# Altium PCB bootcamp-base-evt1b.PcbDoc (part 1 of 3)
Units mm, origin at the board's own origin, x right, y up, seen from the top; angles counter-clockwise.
Board outline 49.31 x 77.41 mm, 4 copper layers (Top Layer, Internal Plane 1, Internal Plane 2, Bottom Layer), stack 1.597 mm thick; 178 components, 122 nets, 1398 pads, 353 vias.
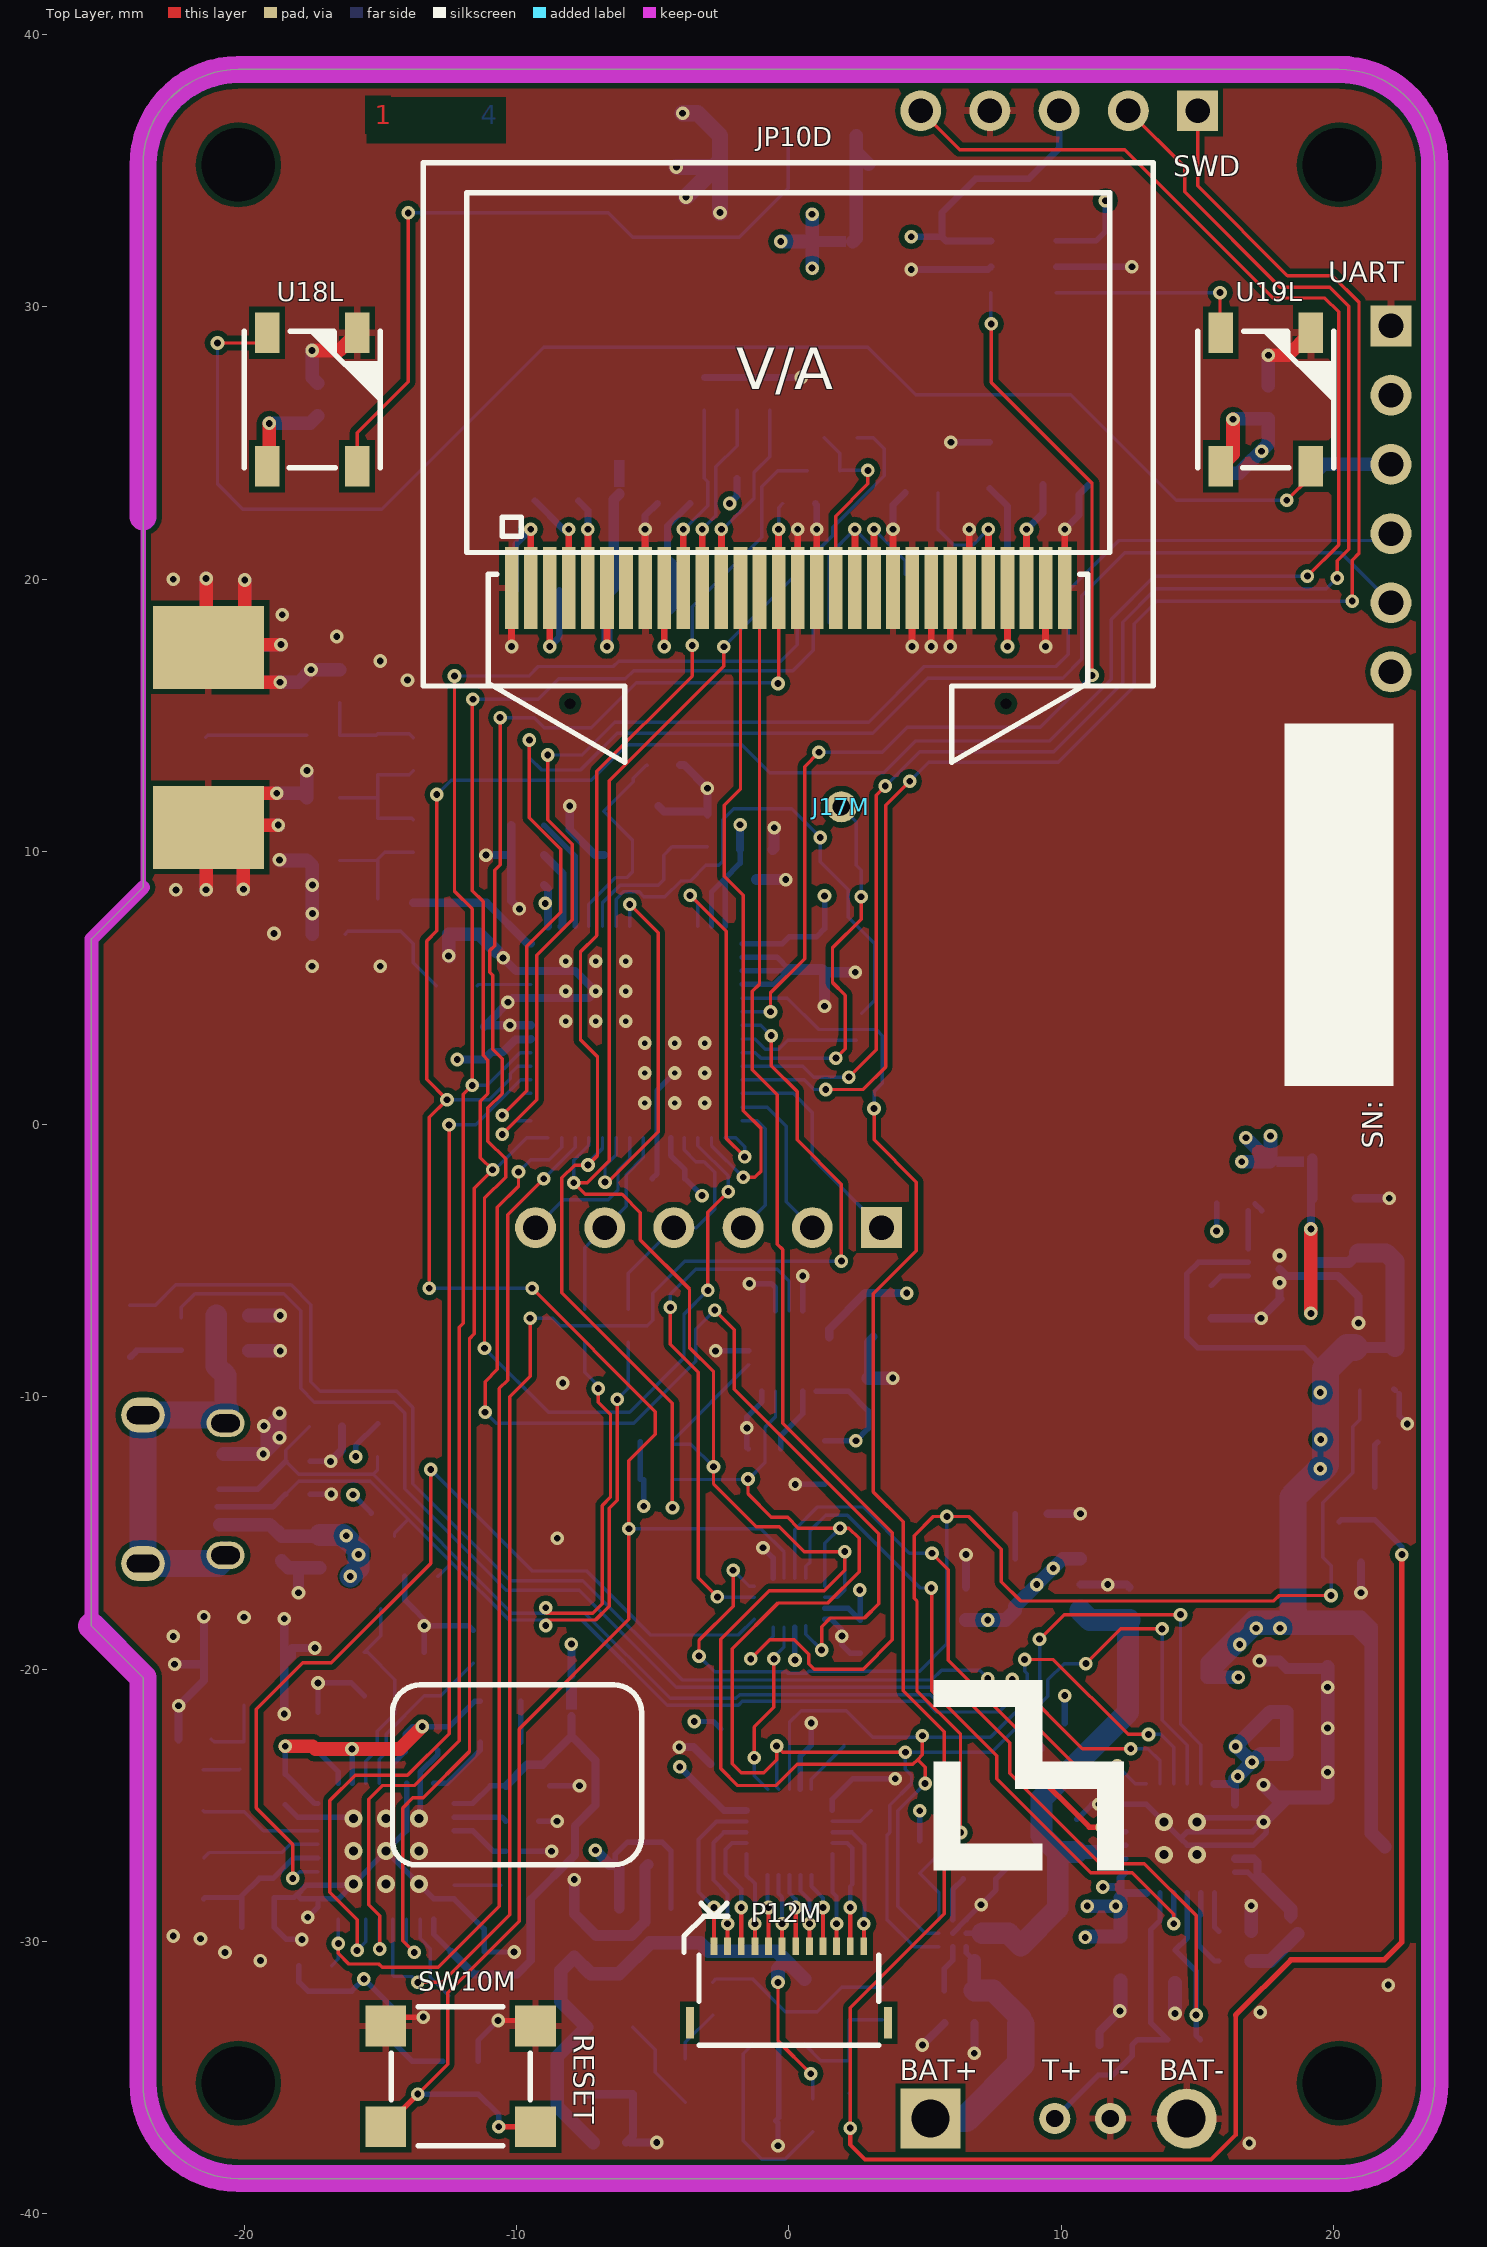
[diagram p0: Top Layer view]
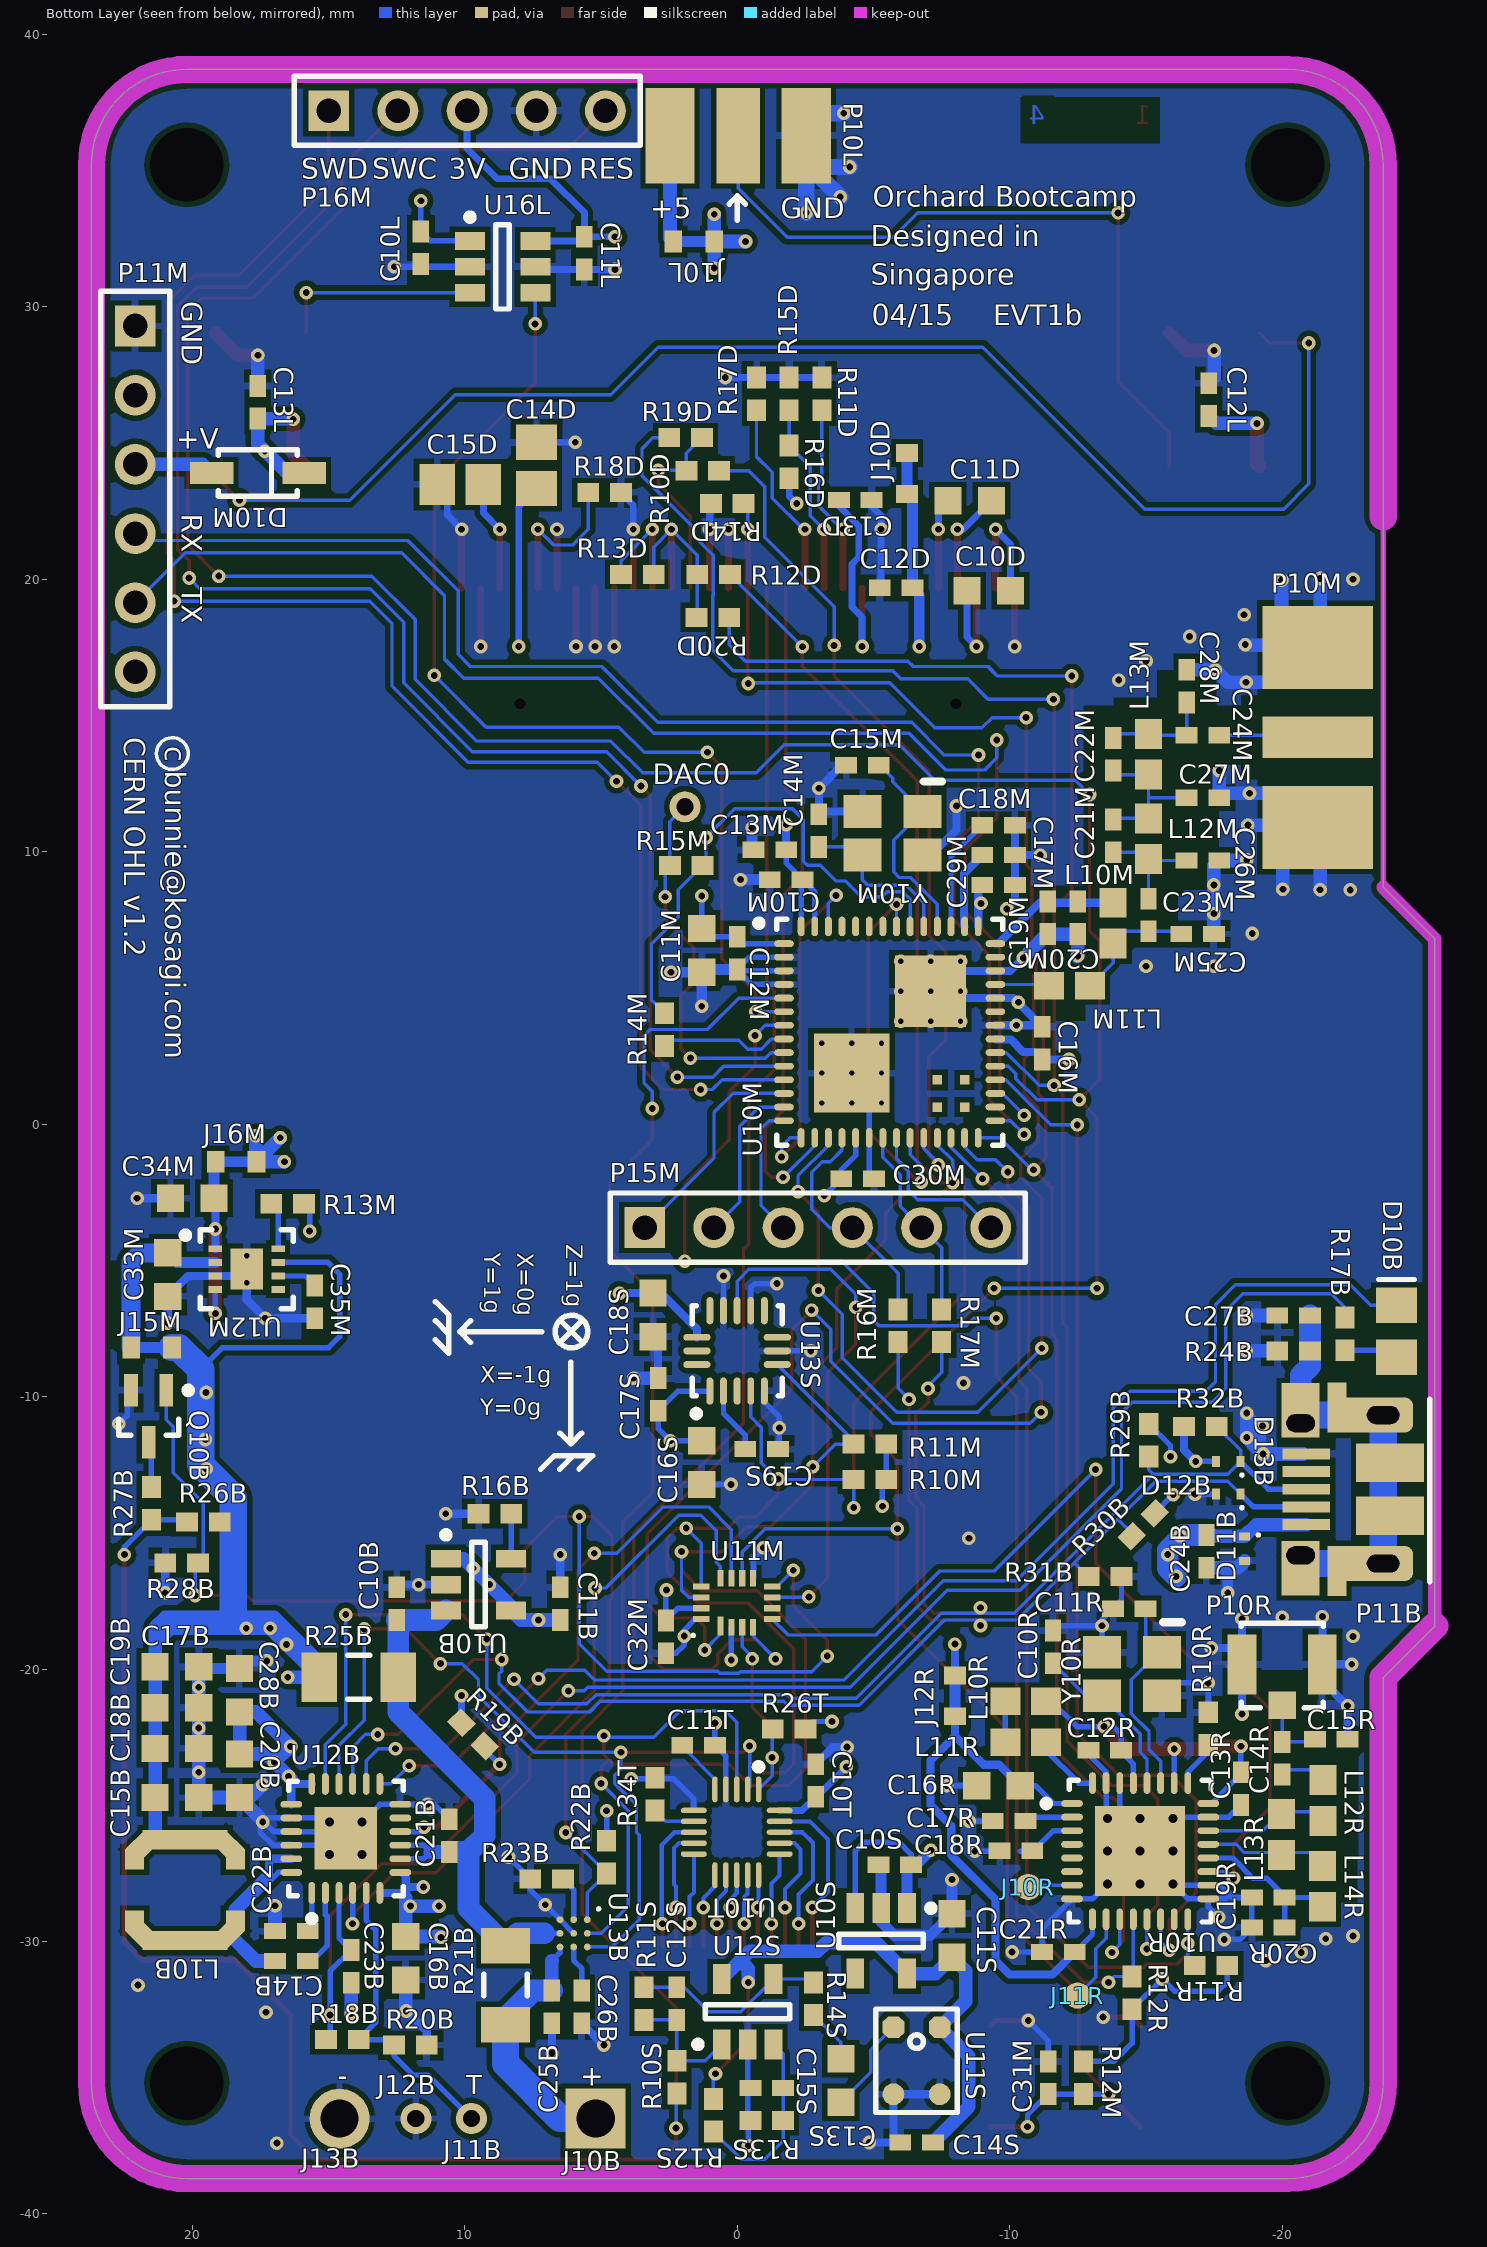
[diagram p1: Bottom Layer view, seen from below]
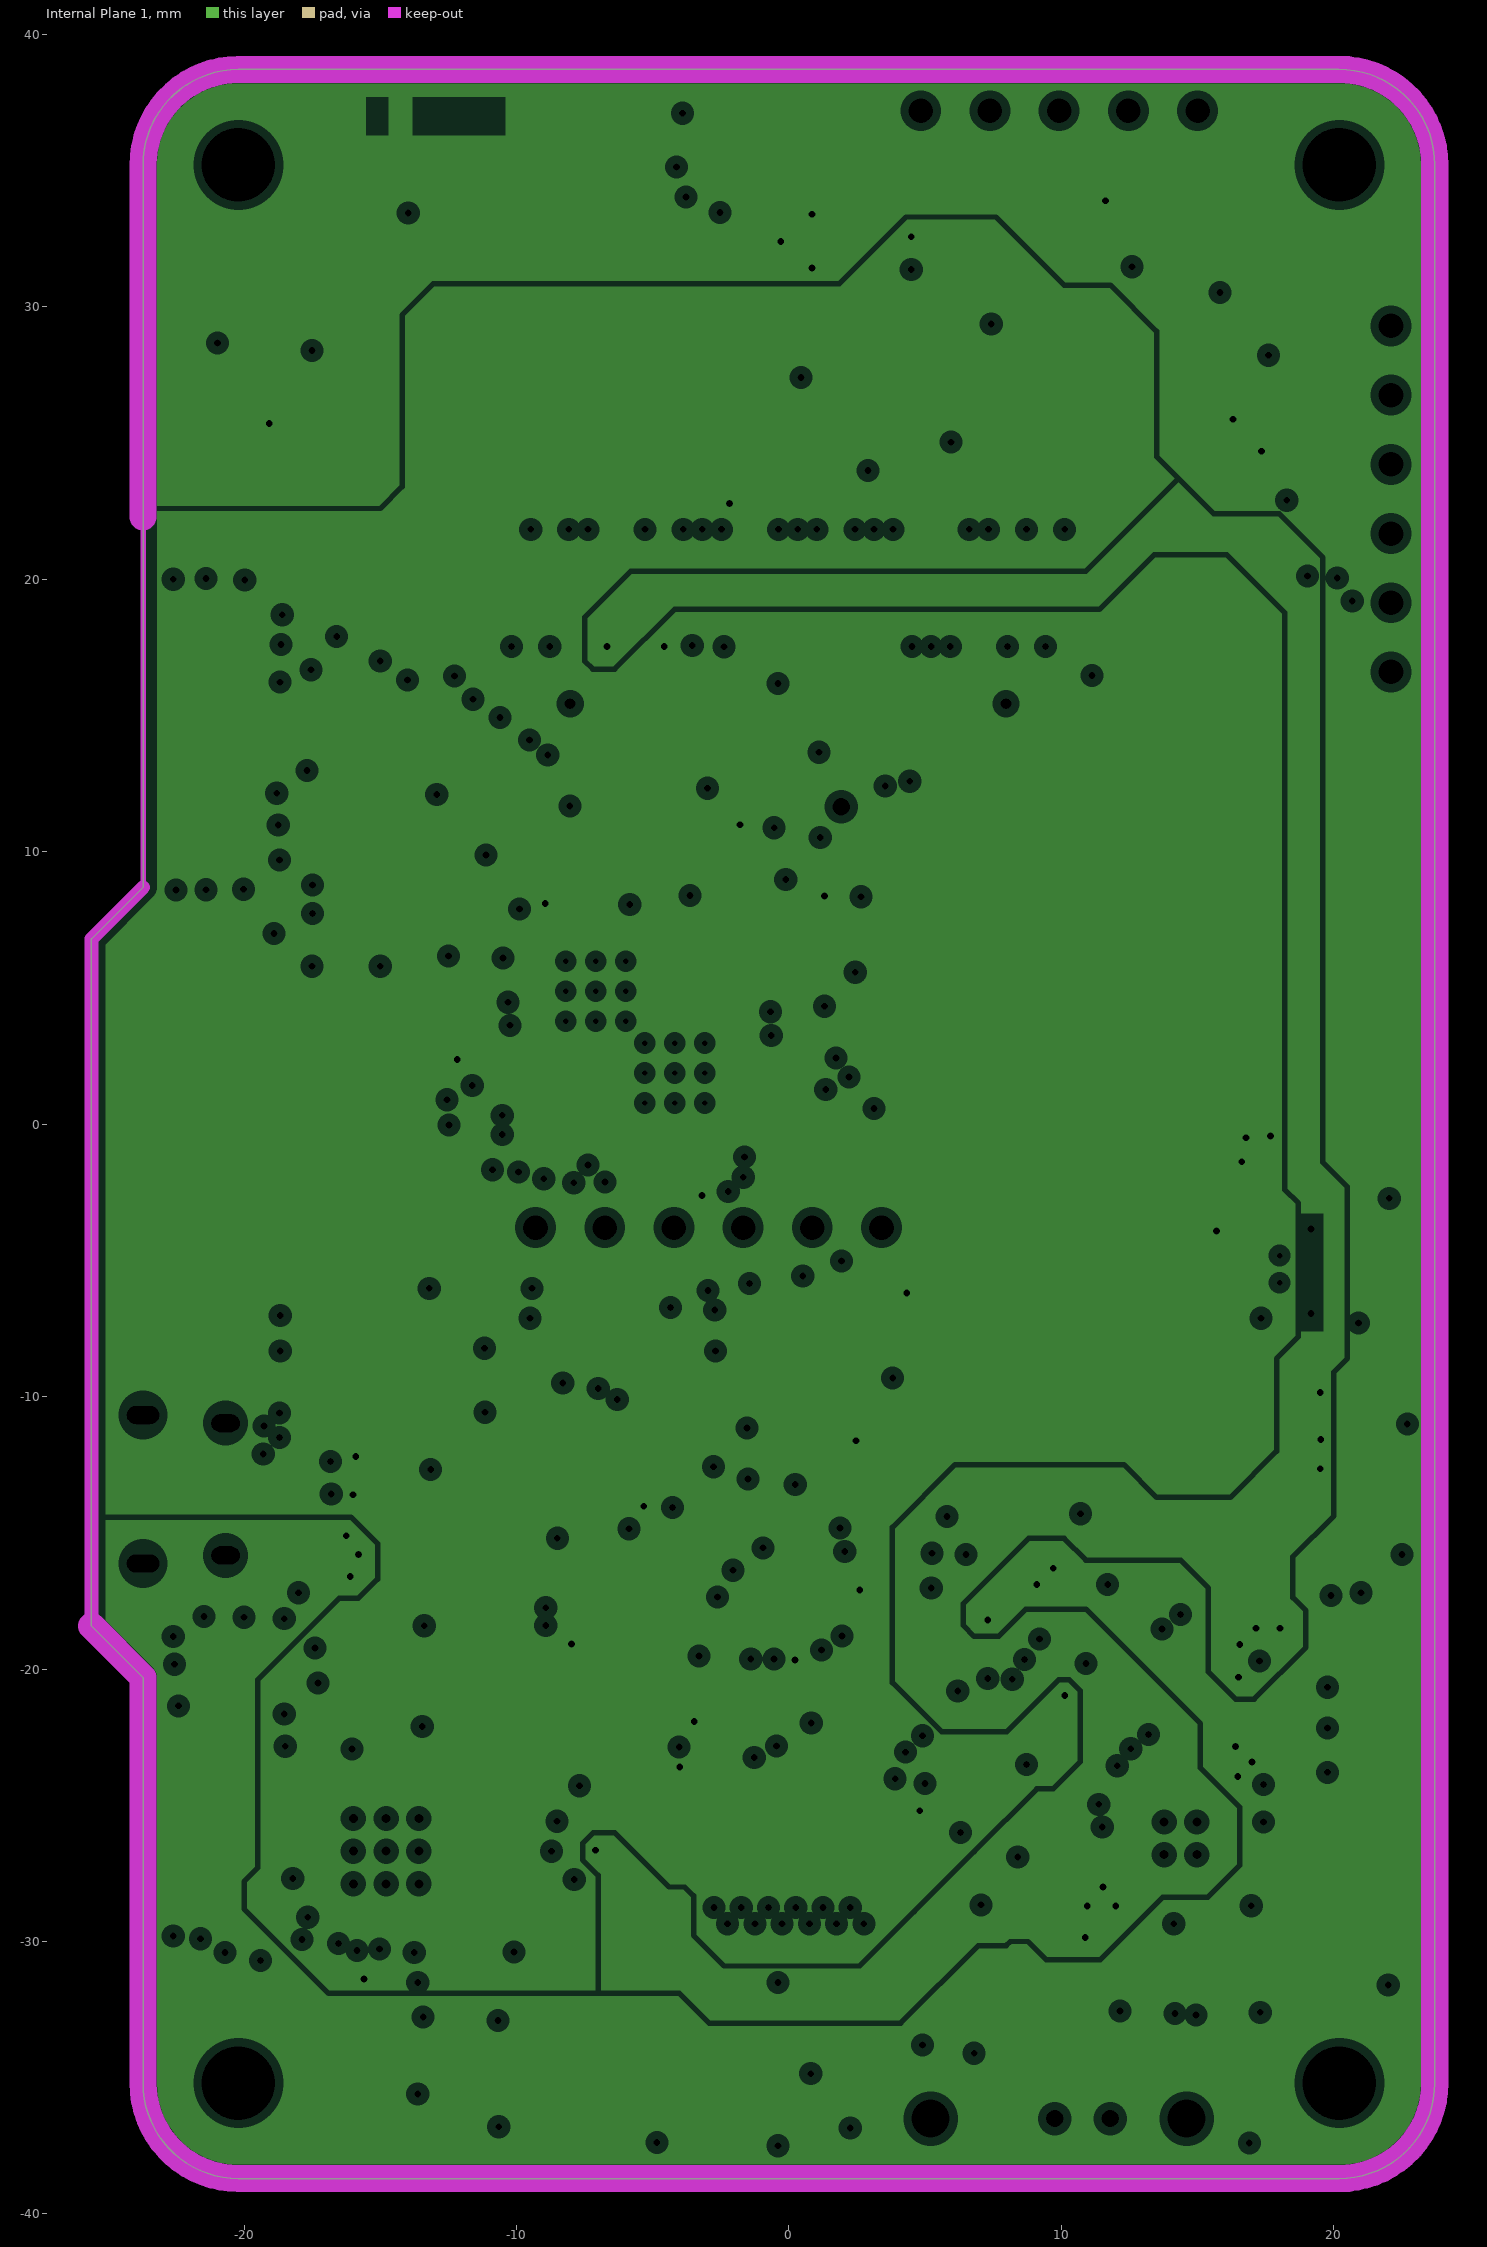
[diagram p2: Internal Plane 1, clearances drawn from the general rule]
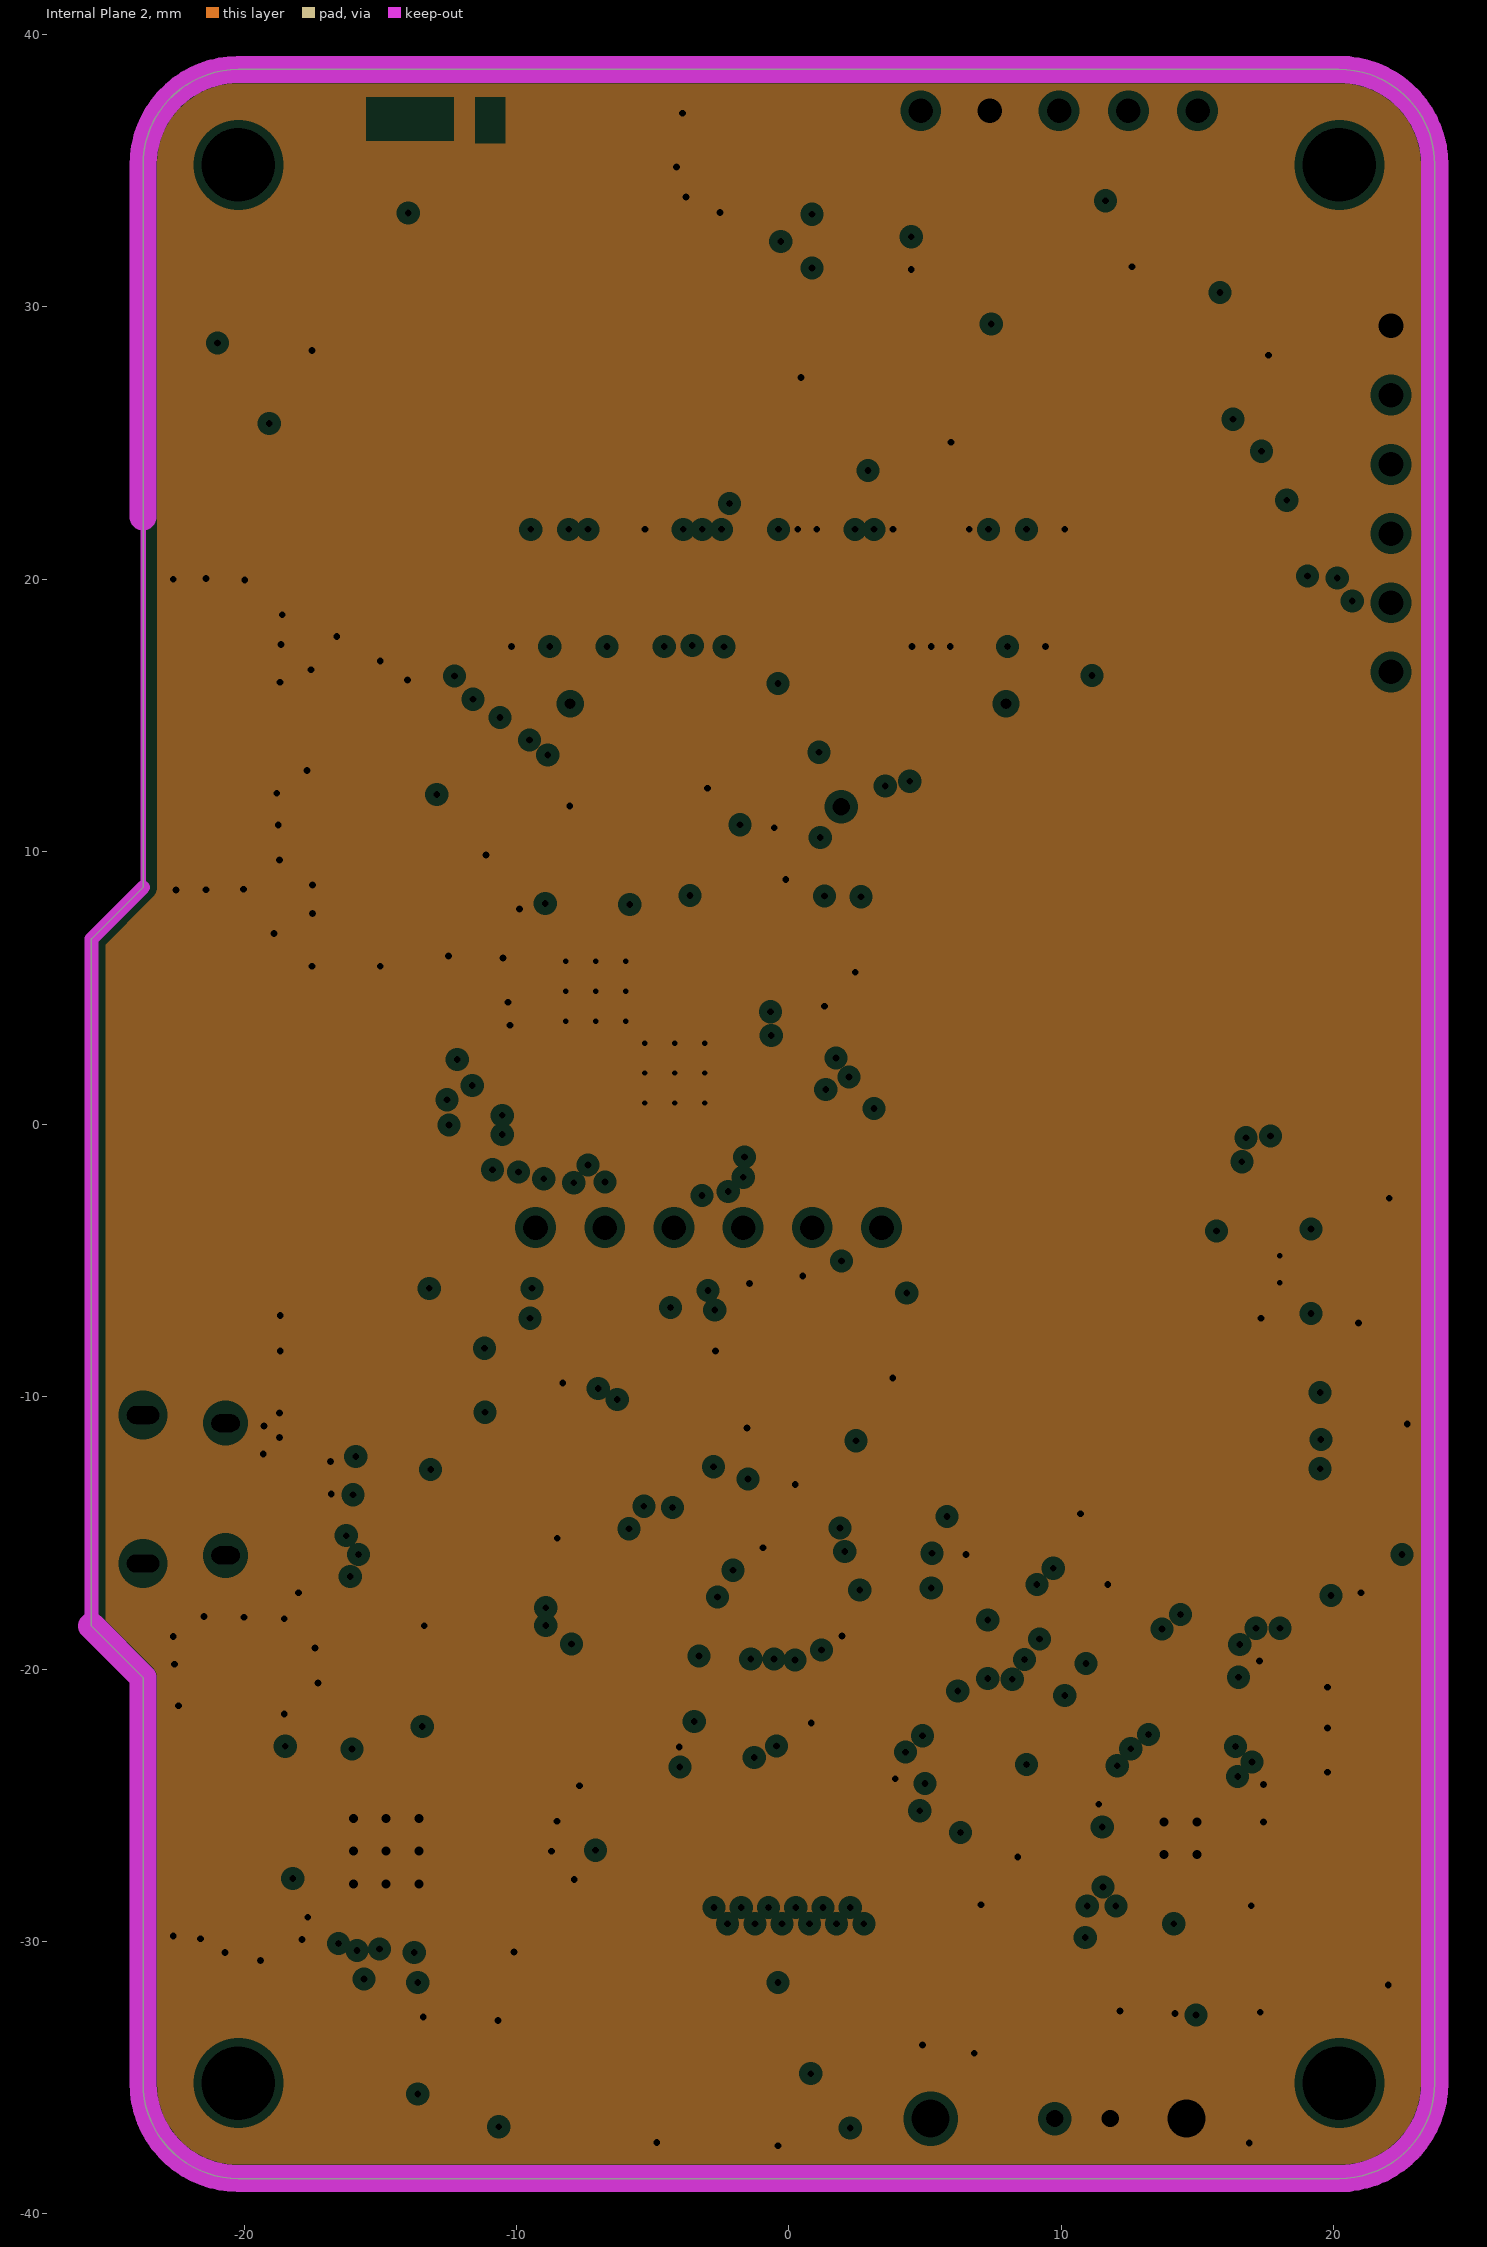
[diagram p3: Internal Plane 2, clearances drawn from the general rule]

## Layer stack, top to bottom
Top Solder: solder mask 0.0102, Solder Resist, Dk 3.5
Top Layer: signal copper 0.0356
Dielectric 1: core 0.1, FR-4, Dk 4.2
Internal Plane 1: plane copper 0.036, net P3.0V
Dielectric 3: prepreg 1.1, Dk 4.2
Internal Plane 2: plane copper 0.036, net GND
Dielectric 2: core 0.254, Dk 4.2
Bottom Layer: signal copper 0.0356
Bottom Solder: solder mask 0.0102, Solder Resist, Dk 3.5

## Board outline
-25.6,-18.417 -23.707,-20.31 -23.707,-35.2 ccw(c-20.207,-35.2) -20.207,-38.7 20.194,-38.7 ccw(c20.207,-35.2) 23.707,-35.2 23.707,-35.186 23.707,35.214 ccw(c20.207,35.214) 20.179,38.714 -20.207,38.714 ccw(c-20.207,35.214) -23.707,35.2 -23.707,8.693 -25.6,6.8

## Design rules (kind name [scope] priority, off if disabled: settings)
AssemblyTestPointUsage [All] p1 off:
AssemblyTestpoint [All] p1 off: testpointundercomponent=TRUE minsize=1.016 maxsize=2.54 preferedsize=1.524 minholesize=0 maxholesize=1.016 preferedholesize=0.813 testpointgrid=0.025 usegrid=TRUE gridtolerance=0 allowsidetop=TRUE allowsidebottom=TRUE
Clearance Poly_bt [InPoly vs InNetClass('RF')] p1: gap=0.8
Clearance Poly_diffpairs [InPoly vs InDifferentialPairClass('All Differential Pairs')] p2: gap=0.63
Clearance Poly_plane [InPoly] p3: gap=0.2
Clearance Pad_NPTH [PadIsPlated = 'False'] p4: gap=0.3
Clearance [All] p5: gap=0.125
ComponentClearance [All] p1 off: gap=0.254 collisioncheckmode=3 verticalgap=0.254 showdistances=FALSE
DiffPairsRouting [All] p1: maxlimit=0.5 minlimit=0.125 mostfreqgap=0.125 toplayer_minwidth=0.1 toplayer_maxwidth=0.1 toplayer_prefwidth=0.1 bottomlayer_minwidth=0.1 bottomlayer_maxwidth=0.1 bottomlayer_prefwidth=0.1 maxuncoupledlength=12.7
HoleSize [All] p1: absolutevalues=TRUE maxlimit=3 minlimit=0.025 maxpercent=80.000 minpercent=20.000
MinimumSolderMaskSliver [All] p1 off: minsoldermaskwidth=0.254
PlaneClearance [All] p1: clearance=0.3
PlaneConnect PlaneConnect_pads [IsPad] p1: planeconnectstyle=Relief reliefexpansion=0.508 reliefentries=4 reliefconductorwidth=0.254 reliefairgap=0.254
PlaneConnect [All] p2: planeconnectstyle=Direct reliefexpansion=0.508 reliefentries=4 reliefconductorwidth=0.254 reliefairgap=0.254
PolygonConnect PolygonConnect_via [IsVia] p1: connectstyle=Direct reliefconductorwidth=0.254 reliefentries=4 polygonreliefangle="90 Angle" airgapwidth=0.254
PolygonConnect [All] p2: connectstyle=Relief reliefconductorwidth=0.25 reliefentries=4 polygonreliefangle="90 Angle" airgapwidth=0.2
RoomDefinition 07captouch [InComponentClass('07captouch')] p1 off: confinementstyle=ConfineIn formatcopy=TRUE lockcomponents=FALSE outline 58.372,-48.063 55.972,-48.063 55.972,-40.863 58.372,-40.863
RoomDefinition 06led [InComponentClass('06led')] p2 off: confinementstyle=ConfineIn formatcopy=TRUE lockcomponents=FALSE outline 64.145,28.5 71.372,28.5 71.372,22.9 64.145,22.9
RoomDefinition 05ble [InComponentClass('05ble')] p3 off: confinementstyle=ConfineIn formatcopy=TRUE lockcomponents=FALSE outline 64.245,33.2 65.672,33.2 65.672,29.4 64.245,29.4
RoomDefinition 03sensors [InComponentClass('03sensors')] p4 off: confinementstyle=ConfineIn formatcopy=TRUE lockcomponents=FALSE outline 64.145,-0.563 63.072,-0.563 63.072,6.637 64.145,6.637
RoomDefinition 02battery [InComponentClass('02battery')] p5 off: confinementstyle=ConfineIn formatcopy=TRUE lockcomponents=FALSE outline 64.145,-19.563 66.572,-19.563 66.572,-1.663 64.145,-1.663
RoomDefinition 01mcu-radio [InComponentClass('01mcu-radio')] p6 off: confinementstyle=ConfineIn formatcopy=TRUE lockcomponents=FALSE outline 64.245,-46.763 71.072,-46.763 71.072,-20.763 64.245,-20.763
RoomDefinition 04oled [InComponentClass('04oled')] p7 off: confinementstyle=ConfineIn formatcopy=TRUE lockcomponents=FALSE outline 62.172,-44.116 60.572,-44.116 60.572,-31.216 62.172,-31.216
RoutingVias [All] p1: holewidth=0.25 width=0.5 viastyle="Through Hole" minholewidth=0.25 minwidth=0.45 maxholewidth=0.38 maxwidth=0.76
SilkToBoardRegionClearance [All] p1 off:
SilkToSilkClearance [All] p1 off: silktosilkclearance=0.254
SilkToSolderMaskClearance [IsPad] p1 off: minsilkscreentomaskgap=0.254 clearancetoexposedcopper=TRUE
SolderMaskExpansion [All] p1: expansion=0.07
Width [All] p1: maxlimit=3 minlimit=0.125 preferedwidth=0.125 minimp=50.000000 maximp=50.000000 favimp=50.000000
18 further rules are at their usual default settings.

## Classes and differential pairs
component class 07captouch: C10T C11T P12M R26T R34T U10T
component class 01mcu-radio: C10M C11M C12M C13M C14M C15M C16M C17M C18M C19M C20M C21M C22M C23M C24M C25M C26M C27M C28M C29M C30M C31M C32M C33M C34M C35M D10M J15M J16M J17M L10M L11M L12M L13M NT10M P10M P11M P15M P16M R10M R11M R12M R13M R14M R15M R16M R17M SW10M U10M U11M U12M Y10M
component class 02battery: C10B C11B C14B C15B C16B C17B C18B C19B C20B C21B C22B C23B C24B C25B C26B C27B C28B D10B D11B D12B D13B J10B J11B J12B J13B L10B NT10B P11B Q10B R16B R17B R18B R19B R20B R21B R22B R23B R24B R25B R26B R27B R28B R29B R30B R31B R32B U10B U12B U13B
component class 03sensors: C10S C11S C12S C13S C14S C15S C16S C17S C18S C19S R10S R11S R12S R13S R14S U10S U11S U12S U13S
component class 04oled: C10D C11D C12D C13D C14D C15D J10D JP10D R10D R11D R12D R13D R14D R15D R16D R17D R18D R19D R20D
component class 05ble: C10R C11R C12R C13R C14R C15R C16R C17R C18R C19R C20R C21R J10R J11R J12R L10R L11R L12R L13R L14R P10R R10R R11R R12R U10R Y10R
component class 06led: C10L C11L C12L C13L J10L P10L U16L U18L U19L
net class RF: BLE_ANT BLE_ANT1 BLE_ANT2 NetC14R_1 NetC21M_1 NetC21M_2 NetC22M_2 NetC24M_2 RFIO

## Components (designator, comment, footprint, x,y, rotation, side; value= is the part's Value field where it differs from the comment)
C10B "1.0uF, 10V, X5R" CAPC1005N 12.5,-17.6 r90 bottom
C10D "1.0uF, 25V, X5R" CAPC1608N -9.228,19.584 r180 bottom
C10L "0.1uF, 25V, X5R" CAPC1005N 11.616,32.172 r270 bottom
C10M "0.1uF, 6.3V, X5R" CAPC1005N -1.792,8.979 r0 bottom
C10R "7.5pF, 50V, NP0, +/-0.5pF" CAPC1005N -11.586,-19.184 r90 bottom
C10S "0.1uF, 6.3V, X5R" CAPC1005N -5.779,-27.177 r0 bottom
C10T "0.1uF, 6.3V, X5R" CAPC1005N -2.878,-24.091 r90 bottom
C11B "1.0uF, 10V, X5R" CAPC1005N 6.5,-17.6 r90 bottom
C11D "1.0uF, 25V, X5R" CAPC1608N -8.528,22.884 r180 bottom
C11L "0.1uF, 6.3V, X5R" CAPC1005N 5.616,31.972 r270 bottom
C11M "10uF, 10V, X5R" CAPC1608N 1.308,6.379 r270 bottom
C11R "7.5pF, 50V, NP0, +/-0.5pF" CAPC1005N -14.386,-17.784 r0 bottom
C11S "4.7uF, 10V, X5R" CAPC1608N -7.879,-29.777 r90 bottom
C11T "0.1uF, 6.3V, X5R" CAPC1005N 1.422,-22.791 r180 bottom
C12D "1.0uF, 10V, X5R" CAPC1005N -5.828,19.684 r0 bottom
C12L "1.0uF, 10V, X5R" CAPC1005N -17.3,26.6 r90 bottom
C12M "0.01uF, 10V, X7R" CAPC1005N 0.008,6.279 r270 bottom
C12R "1.0uF, 10V, X5R" CAPC1005N -13.486,-22.984 r0 bottom
C12S "330pF, 10V, NP0, 5%" CAPC1005N 2.221,-32.277 r90 bottom
C13D "1.0uF, 10V, X5R" CAPC1005N -4.328,22.909 r180 bottom
C13L "1.0uF, 10V, X5R" CAPC1005N 17.6,26.5 r90 bottom
C13M "0.1uF, 6.3V, X5R" CAPC1005N -1.192,10.079 r0 bottom
C13R "1nF, 50V, X7R" CAPC1005N -18.486,-24.384 r270 bottom
C13S "10uF, 10V, X5R" CAPC1608N -3.8,-35.1 r90 bottom
C14B "0.033uF, 16V, X7R" CAPC1005N 16.372,-30.716 r0 bottom
C14D "4.7uF, 25V, X7R" CAPC2012N 7.372,24.184 r90 bottom
C14M "7.5pF, 50V, NP0, +/-0.5pF" CAPC1005N -2.992,10.779 r90 bottom
C14R "1.8pF, 50V, NP0, +/-0.10pF" CAPC1005N -20,-23.275 r90 bottom
C14S "0.1uF, 6.3V, X5R" CAPC1005N -6.579,-37.377 r0 bottom
C15B "10uF, 10V, X5R" CAPC1608N 20.572,-24.716 r180 bottom
C15D "4.7uF, 25V, X7R" CAPC2012N 10.172,23.484 r0 bottom
C15M "7.5pF, 50V, NP0, +/-0.5pF" CAPC1005N -4.592,13.179 r0 bottom
C15R "1.2pF, 50V, NP0, +/-0.10pF" CAPC1005N -21.8,-22.575 r0 bottom
C15S "1.0uF, 10V, X5R" CAPC1005N -1.079,-35.377 r0 bottom
C16B "10uF, 10V, X5R" CAPC1608N 12.172,-30.616 r270 bottom
C16M "0.1uF, 6.3V, X5R" CAPC1005N -11.192,2.979 r90 bottom
C16R "4.7uF, 10V, X5R" CAPC1608N -9.586,-24.284 r0 bottom
C16S "10uF, 10V, X5R" CAPC1608N 1.308,-12.421 r270 bottom
C17B "10uF, 10V, X5R" CAPC1608N 20.572,-19.916 r180 bottom
C17M "0.1uF, 6.3V, X5R" CAPC1005N -9.592,9.879 r180 bottom
C17R "0.1uF, 6.3V, X5R" CAPC1005N -9.975,-25.575 r0 bottom
C17S "0.1uF, 6.3V, X5R" CAPC1005N 2.908,-9.921 r90 bottom
C18B "10uF, 10V, X5R" CAPC1608N 20.572,-22.916 r180 bottom
C18M "0.1uF, 6.3V, X5R" CAPC1005N -9.592,10.979 r180 bottom
C18R "0.033uF, 16V, X7R" CAPC1005N -10.225,-26.675 r180 bottom
C18S "10uF, 10V, X5R" CAPC1608N 3.1,-7 r270 bottom
C19B "10uF, 10V, X5R" CAPC1608N 20.572,-21.416 r180 bottom
C19M "0.1uF, 6.3V, X5R" CAPC1005N -11.392,7.579 r270 bottom
C19R "2200pF, 50V, X7R" CAPC1005N -19.486,-28.384 r180 bottom
C19S "0.1uF, 6.3V, X5R" CAPC1005N -0.892,-11.921 r180 bottom
C20B "10uF, 10V, X5R" CAPC1608N 18.272,-23.916 r270 bottom
C20M "220pF, 10V, NP0, 5%" CAPC1005N -12.492,7.579 r270 bottom
C20R "DNP" CAPC1005N -19.486,-29.484 r180 bottom
C21B "1.0uF, 10V, X5R" CAPC1005N 10.572,-26.116 r90 bottom
C21M "0402 DNP" CAPC1005N -13.792,10.579 r90 bottom
C21R "0.1uF, 6.3V, X5R" CAPC1005N -11.786,-30.384 r0 bottom
C22B "1.0uF, 10V, X5R" CAPC1005N 16.372,-29.616 r0 bottom
C22M "0402 DNP" CAPC1005N -13.792,13.579 r90 bottom
C23B "1.0uF, 10V, X5R" CAPC1005N 14.172,-30.916 r270 bottom
C23M "6.8pF, 50V, NP0, +/-0.5pF" CAPC1005N -15.092,7.679 r90 bottom
C24B "0.1uF, 25V, X5R" CAPC1005N -17.223,-15.679 r270 bottom
C24M "100pF, 50V, NP0, 5%" CAPC1005N -17.092,14.279 r180 bottom
C25B "1.0uF, 10V, X5R" CAPC1005N 6.808,-32.4 r270 bottom
C25M "2.0pF, 50V, NP0, +/-0.25pF" CAPC1005N -16.892,6.979 r180 bottom
C26B "1.0uF, 10V, X5R" CAPC1005N 5.708,-32.4 r270 bottom
C26M "0402 DNP" CAPC1005N -17.092,9.679 r0 bottom
C27B "0.1uF, 25V, X5R" CAPC1005N -20.421,-7.023 r0 bottom
C27M "7.5pF, 50V, NP0, +/-0.5pF" CAPC1005N -17.092,11.979 r180 bottom
C28B "10uF, 10V, X5R" CAPC1608N 18.275,-20.775 r90 bottom
C28M "5.6pF, 50V, NP0, +/-0.25pF" CAPC1005N -16.492,16.079 r90 bottom
C29M "0.1uF, 6.3V, X5R" CAPC1005N -9.592,8.779 r180 bottom
C30M "0.1uF, 6.3V, X5R" CAPC1005N -4.417,-1.996 r180 bottom
C31M "0.01uF, 10V, X7R" CAPC1005N -11.408,-35 r90 bottom
C32M "0.1uF, 6.3V, X5R" CAPC1005N 2.621,-18.817 r270 bottom
C33M "4.7uF, 10V, X5R" CAPC1608N 20.908,-5.521 r270 bottom
C34M "4.7uF, 10V, X5R" CAPC1608N 20.008,-2.721 r0 bottom
C35M "0.033uF, 16V, X7R" CAPC1005N 15.508,-6.521 r90 bottom
D10B "White LED" CD2012-0805 -24.2,-7.6 r90 bottom
D10M "B140HW-7" SOD123 17.6,23.9 r180 bottom
D11B "ESD9B5.0ST5G" SOD-923 -18.623,-15.579 r270 bottom
D12B "ESD9B5.0ST5G" SOD-923 -18.023,-13.579 r0 bottom
D13B "ESD9B5.0ST5G" SOD-923 -18.023,-12.379 r0 bottom
J10B "wire hole" TP_HOLE#1 5.2,-36.5 r90 bottom
J10D "power tap (DNP)" RESTAP-0603 -6.228,23.884 r90 bottom
J10L "power tap (DNP)" RESTAP-0603 1.6,32.4 r0 bottom
J10R "test point (DNP)" TP_SMT_38mil -10.675,-28 r90 bottom
J11B "wire hole" TP_HOLE#2 9.76,-36.5 r180 bottom
J11R "test point (DNP)" TP_SMT_38mil -12.486,-31.984 r90 bottom
J12B "wire hole" TP_HOLE#2 11.8,-36.5 r0 bottom
J12R "power tap (DNP)" RESTAP-0603 -7.986,-20.984 r270 bottom
J13B "wire hole" TP_HOLE#3 14.6,-36.5 r270 bottom
J15M "power tap (DNP)" RESTAP-0603 21.5,-8.2 r180 bottom
J16M "power tap (DNP)" RESTAP-0603 18.4,-1.379 r180 bottom
J17M "wire hole" TP_HOLE#2 1.925,11.65 r180 top
JP10D "ER-OLED0.96-3W" ER-OLED0.96-FOLD -0.028,20.184 r0 top locked
L10B "2.2uH LPS4018-222" COILCRAFT_LPS4018 20.272,-28.116 r90 bottom
L10M "33nH 5% Q>8" INDC1608AN -13.792,7.379 r270 bottom
L10R "15nH, Q>35, 5%" INDC1608AN -10.586,-21.184 r180 bottom
L11M "4.7nH+/-0.3nH Q>8" INDC1608AN -12.192,5.079 r180 bottom
L11R "10uH, 300mA" INDC1608AN -10.586,-22.684 r0 bottom
L12M "6.8nH 5% Q>8" INDC1608AN -15.092,10.479 r90 bottom
L12R "3.9nH+/-0.3nH Q>8" INDC1608AN -21.5,-24.825 r90 bottom
L13M "6.8nH 5% Q>8" INDC1608AN -15.092,13.579 r90 bottom
L13R "8.2nH+/-0.3nH Q>8" INDC1608AN -19.975,-26.075 r270 bottom
L14R "5.6nH+/-0.3nH Q>8" INDC1608AN -21.475,-27.975 r270 bottom
P10L "WS2812B-PAD" LED_STRIP_PADS_SHORT -0.028,36.284 r270 bottom
P10M "SMA Edge Launch" SMA_EDGELAUNCH -21.307,14.2 r180 bottom
P10R "U.FL KAWEEI P1163-0140R" HRS_U.FL -20,-19.825 r180 bottom
P11B "FCI 10103594-0001LF" USB_MICRO_B_SMT -23.707,-13.4 r90 bottom
P11M "Male 2.54mm 6x1 header (DNP)" HDR1X6 22.1,29.3 r270 bottom
P12M "KAWEEI THD0510-12RL-GF" KAWEEI_THD0510_12RL_GF 0,-30.5 r0 top
P15M "2.54mm header, 6 pin" HDR1X6 3.398,-3.796 r180 bottom
P16M "Header 5" HDR1X5 15,37.2 r180 bottom
Q10B "2N7002W (DNP)" SOT323-3AN 21.608,-10.721 r270 bottom
R10D "0 ohm (DNP)" RESC1005N 1.272,23.984 r180 bottom
R10M "4.7k, 1%" RESC1005N -4.863,-13.041 r180 bottom
R10R "22k, 1%" RESC1005N -17.286,-22.184 r270 bottom
R10S "2.2k, 1%" RESC1005N 2.221,-34.977 r90 bottom
R11D "10k, 1%" RESC1005N -3.103,26.809 r270 bottom
R11M "4.7k, 1%" RESC1005N -4.863,-11.741 r180 bottom
R11R "4.7k, 1%" RESC1005N -17.386,-30.884 r180 bottom
R11S "22k, 1%" RESC1005N 3.421,-32.277 r270 bottom
R12D "0 ohm (DNP)" RESC1005N 0.872,20.184 r180 bottom
R12M "1k, 1%" RESC1005N -12.708,-35 r270 bottom
R12R "4.7k, 1%" RESC1005N -14.486,-31.884 r270 bottom
R12S "47k, 1%" RESC1005N 0.877,-36.379 r90 bottom
R13D "0 ohm (DNP)" RESC1005N 3.672,20.184 r180 bottom
R13M "100k, 1%" RESC1005N 16.508,-2.921 r0 bottom
R13S "47k, 1%" RESC1005N -1.079,-36.577 r180 bottom
R14D "10k, 1% (DNP)" RESC1005N 0.372,22.784 r0 bottom
R14M "0 ohm" RESC1005N 2.675,3.475 r270 bottom
R14S "2.2k, 1%" RESC1005N -2.8,-32.1 r270 bottom
R15D "10k, 1%" RESC1005N -1.903,26.809 r270 bottom
R15M "0 ohm (DNP)" RESC1005N 1.875,9.5 r0 bottom
R16B "2k, 1%" RESC1005N 8.9,-14.3 r0 bottom
R16D "10k, 1% (DNP)" RESC1005N -1.903,24.309 r90 bottom
R16M "0 ohm" RESC1005N -5.9,-7.4 r90 bottom
R17B "470, 1%" RESC1005N -22.3,-7.7 r270 bottom
R17D "10k, 1%" RESC1005N -0.703,26.809 r270 bottom
R17M "0 ohm" RESC1005N -7.5,-7.4 r90 bottom
R18B "9.76k, 1%" RESC1005N 14.5,-33.6 r0 bottom
R18D "390k, 1%" RESC1005N 4.872,23.184 r180 bottom
R19B "47k, 1%" RESC1005N 9.7,-22.4 r45 bottom
R19D "0 ohm" RESC1005N 1.9,25.2 r0 bottom
R20B "34.8k, 1%" RESC1005N 12,-33.8 r0 bottom
R20D "0 ohm" RESC1005N 0.9,18.6 r180 bottom
R21B "0 ohm 1206 (DNP)" RESC3216N 8.508,-31.6 r270 bottom
R22B "10k, 1%" RESC1005N 4.8,-26.9 r90 bottom
R23B "10k, 1%" RESC1005N 7,-27.7 r180 bottom
R24B "100, 1%" RESC1005N -20.421,-8.323 r0 bottom
R25B "0 ohm 1206 (DNP)" RESC3216N 13.9,-20.3 r0 bottom
R26B "10k, 1% (DNP)" RESC1005N 19.6,-14.6 r180 bottom
R26T "4.7k, 1%" RESC1005N -1.9,-22.2 r180 bottom
R27B "10k, 1% (DNP)" RESC1005N 21.508,-13.921 r270 bottom
R28B "10k, 1% (DNP)" RESC1005N 20.4,-16.1 r180 bottom
R29B "10k, 1% (DNP)" RESC1005N -15.1,-11.6 r90 bottom
R30B "1.5k, 1% (DNP)" RESC1005N -14.9,-14.7 r135 bottom
R31B "100k, 1% (DNP)" RESC1005N -13.5,-16.6 r180 bottom
R32B "DNP" RESC1005N -17,-11.1 r0 bottom
R34T "75k, 1%" RESC1005N 3.022,-24.591 r270 bottom
SW10M "5x5mm 1.6mm tall PB" SWITCH_TS-1187A -9.3,-33.1 r270 top
U10B "MCP73812T-420I/OT (DNP)" SOT-23-OT5_N 9.5,-16.9 r180 bottom
U10M "MKW01Z128CHN" KINETIS_W_QFN50P800X800X98_HS-57N -5.592,3.379 r180 bottom
U10R "NRF8001" QFN50P500X500-32VAN -14.786,-26.684 r180 bottom
U10S "LP2980IM5-3.0" SOT23-5AN -5.279,-29.977 r270 bottom
U10T "MPR121" QFN40P300X300X60-20N 0.022,-25.991 r270 bottom
U11M "FXL6408UMX" FAIRCHILD_UMLP16 0.021,-17.567 r90 bottom
U11S "SPU0409HD5H-PB" KNOWLES_SPU0409HD5H-PB -6.579,-34.377 r180 bottom
U12B "BQ24260RGET" QFN50P400X400-24VBN 14.372,-26.216 r90 bottom
U12M "LP3982ILD-3.0" LDA08C 18.008,-5.321 r180 bottom
U12S "FAN4174IS5X" SOT23-5AN -0.379,-32.577 r90 bottom
U13B "BQ27421YZFT-G1A" TI_YZF_S_XBGA_N9 6.008,-29.7 r270 bottom
U13S "MMA8452QR1" FSC_QFN_3x3x1_16_2077-02 0.008,-8.321 r90 bottom
U16L "SN74LVC1T45DBV" SOT26A-6N 8.616,31.472 r180 bottom
U18L "WS2812B" WS2812B -17.5,26.6 r90 top
U19L "WS2812B" WS2812B 17.5,26.6 r90 top
Y10M "32.000MHz" NDK_NX3225SA -6.792,11.479 r0 bottom
Y10R "16.000MHz" NDK_NX3225SA -15.586,-19.384 r0 bottom

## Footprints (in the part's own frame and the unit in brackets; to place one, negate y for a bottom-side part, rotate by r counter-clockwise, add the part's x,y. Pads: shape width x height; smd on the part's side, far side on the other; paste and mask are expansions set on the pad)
CAPC1005N [mm] "Chip Capacitor, Body 1.0x0.5mm, IPC Medium Density"
  rect 0.8x0.6 smd: 1(-0.6,0) 2(0.6,0)
  body extent -0.55,-0.3 0.55,0.3, height 0.6
CAPC1608N [mm] "Chip Capacitor, Body 1.6x0.8mm, IPC Medium Density"
  rect 1x1 smd: 1(-0.8,0) 2(0.8,0)
  body extent -0.87,-0.48 0.87,0.48, height 0.85
CAPC2012N [mm] "Chip Capacitor, Body 2.0x1.3mm, IPC Medium Density"
  rect 1.3x1.5 smd: 1(-0.85,0) 2(0.85,0)
  body extent -1.1,-0.72 1.1,0.72, height 1.1
CD2012-0805 [mm] "Chip Diode; Body 2.0 x 1.3 mm (LxW typ)"
  rect 1.3x1.5 smd: 1(-0.95,0) 2(0.95,0)
  silkscreen extent 1.9,-0.65 1.9,0.65
COILCRAFT_LPS4018 [mm] "Coilcraft SMT power inductor, shielded, high current"
  rect 0.7x3.124 smd mask+0.07: 1(-1.85,0) 2(1.85,0)
  rect 0.7x1 smd rot 135 mask+0.07: 1(-1.6,1.6) 2(1.6,-1.6)
  rect 0.7x1 smd rot 45 mask+0.07: 1(-1.6,-1.6) 2(1.6,1.6)
  rect 0.75x0.7 smd mask+0.07: 1(-1.125,-1.85) 1(-1.125,1.85) 2(1.125,-1.85) 2(1.125,1.85)
  body extent -2.05,-2.05 2.05,2.05, height 1.8
ER-OLED0.96-FOLD [mm] "ER-OLED 0.96in Direct to PCB mount, folded"
  round 0.2 hole 0.4 unplated mask+0.3: 0(-8,-4.75) 0(8,-4.75)
  rect 0.5x3 smd mask+0.07: 1(-10.15,-0.5) 2(-9.45,-0.5) 3(-8.75,-0.5) 4(-8.05,-0.5) 5(-7.35,-0.5) 6(-6.65,-0.5) 7(-5.95,-0.5) 8(-5.25,-0.5) 9(-4.55,-0.5) 10(-3.85,-0.5) 11(-3.15,-0.5) 12(-2.45,-0.5) 13(-1.75,-0.5) 14(-1.05,-0.5) 15(-0.35,-0.5) 16(0.35,-0.5) 17(1.05,-0.5) 18(1.75,-0.5) 19(2.45,-0.5) 20(3.15,-0.5) 21(3.85,-0.5) 22(4.55,-0.5) 23(5.25,-0.5) 24(5.95,-0.5) 25(6.65,-0.5) 26(7.35,-0.5) 27(8.05,-0.5) 28(8.75,-0.5) 29(9.45,-0.5) 30(10.15,-0.5)
  silkscreen extent -13.4,-6.9 13.4,15.1, body extent -13.4,-4.1 13.4,15.1, height 1.61
FAIRCHILD_UMLP16 [mm] "Fairchild 16-pin UMLP"
  rect 0.7x0.225 smd mask+0.07: 1(-0.85,0.6)
  rect 0.6x0.225 smd mask+0.07: 2(-0.9,0.2) 3(-0.9,-0.2) 4(-0.9,-0.6) 9(0.9,-0.6) 10(0.9,-0.2) 11(0.9,0.2) 12(0.9,0.6)
  rect 0.225x0.6 smd mask+0.07: 5(-0.6,-1.3) 6(-0.2,-1.3) 7(0.2,-1.3) 8(0.6,-1.3) 13(0.6,1.3) 14(0.2,1.3) 15(-0.2,1.3) 16(-0.6,1.3)
  silkscreen extent -1.25,1.55 -1.15,1.65, body extent -0.9,-1.3 0.9,1.3, height 0.55
FSC_QFN_3x3x1_16_2077-02 [mm] "16-pin non-standard Freescale QFN package"
  oval 1x0.25 smd mask+0.07: 1(-1.475,1) 2(-1.475,0.5) 3(-1.475,0) 4(-1.475,-0.5) 5(-1.475,-1) 9(1.475,-1) 10(1.475,-0.5) 11(1.475,0) 12(1.475,0.5) 13(1.475,1)
  oval 0.25x1 smd mask+0.07: 6(-0.5,-1.475) 7(0,-1.475) 8(0.5,-1.475) 14(0.5,1.475) 15(0,1.475) 16(-0.5,1.475)
  silkscreen extent -2.42,-1.65 1.65,1.65, body extent -1.5,-1.5 1.5,1.5, height 1
HDR1X5 [mm] "Connector; Header; 5 Position"
  rect 1.5x1.5 hole 0.9: 1(0,0)
  round 1.5 hole 0.9: 2(2.54,0) 3(5.08,0) 4(7.62,0) 5(10.16,0)
  silkscreen extent -1.27,-1.27 11.43,1.27
HDR1X6 [mm] "Connector; Header; 6 Position"
  rect 1.5x1.5 hole 0.9: 1(0,0)
  round 1.5 hole 0.9: 2(2.54,0) 3(5.08,0) 4(7.62,0) 5(10.16,0) 6(12.7,0)
  silkscreen extent -1.27,-1.27 13.97,1.27
HRS_U.FL [mm] "6 GHz U.FL connector (ISM band antennas)"
  rect 1.05x2.2 smd: GND(-1.475,0) GND(1.475,0)
  rect 1x1 smd: SIG(0,-1.5)
  silkscreen extent -1.5,-1.6 1.5,1.5, body extent -1.5,-1.6 1.5,1.5, height 1.24
INDC1608AN [mm] "Chip Inductor, Body 1.6x0.8mm, IPC Medium Density"
  rect 1.1x1 smd: 1(-0.75,0) 2(0.75,0)
  body extent -0.9,-0.5 0.9,0.5, height 1
KAWEEI_THD0510_12RL_GF [mm] "FPC, 12 pins, 0.5mm pitch, bottom contacts"
  rect 0.3x1.15 smd mask+0.07: 0(-3.635,-2.485) 0(3.635,-2.485)
  rect 0.25x0.65 smd mask+0.07: 1(-2.75,0.325) 2(-2.25,0.325) 3(-1.75,0.325) 4(-1.25,0.325) 5(-0.75,0.325) 6(-0.25,0.325) 7(0.25,0.325) 8(0.75,0.325) 9(1.25,0.325) 10(1.75,0.325) 11(2.25,0.325) 12(2.75,0.325)
  silkscreen extent -3.85,-3.3 3.3,1.9, body extent -3.3,-3.3 3.3,0.38, height 1
KINETIS_W_QFN50P800X800X98_HS-57N [mm] "QFN, 56-Leads, Body 8.00x8.00mm, Pitch 0.50mm, Thermal Pad 6.60x6.40mm, IPC Medium Density"
  oval 0.72x0.25 smd mask+0.07: 1(-3.88,3.25) 2(-3.88,2.75) 3(-3.88,2.25) 4(-3.88,1.75) 5(-3.88,1.25) 6(-3.88,0.75) 7(-3.88,0.25) 8(-3.88,-0.25) 9(-3.88,-0.75) 10(-3.88,-1.25) 11(-3.88,-1.75) 12(-3.88,-2.25) 13(-3.88,-2.75) 14(-3.88,-3.25) 29(3.88,-3.25) 30(3.88,-2.75) 31(3.88,-2.25) 32(3.88,-1.75) 33(3.88,-1.25) 34(3.88,-0.75) 35(3.88,-0.25) 36(3.88,0.25) 37(3.88,0.75) 38(3.88,1.25) 39(3.88,1.75) 40(3.88,2.25) 41(3.88,2.75) 42(3.88,3.25)
  oval 0.25x0.72 smd mask+0.07: 15(-3.25,-3.88) 16(-2.75,-3.88) 17(-2.25,-3.88) 18(-1.75,-3.88) 19(-1.25,-3.88) 20(-0.75,-3.88) 21(-0.25,-3.88) 22(0.25,-3.88) 23(0.75,-3.88) 24(1.25,-3.88) 25(1.75,-3.88) 26(2.25,-3.88) 27(2.75,-3.88) 28(3.25,-3.88) 43(3.25,3.88) 44(2.75,3.88) 45(2.25,3.88) 46(1.75,3.88) 47(1.25,3.88) 48(0.75,3.88) 49(0.25,3.88) 50(-0.25,3.88) 51(-0.75,3.88) 52(-1.25,3.88) 53(-1.75,3.88) 54(-2.25,3.88) 55(-2.75,3.88) 56(-3.25,3.88)
  rect 0.35x0.35 smd mask+0.07: 57(1.75,-1.75) 58(2.75,-1.75) 59(1.75,-2.75) 60(2.75,-2.75)
  rect 2.62x2.62 smd mask+0.07: 61(1.5,1.5)
  rect 2.77x2.9 smd mask+0.07: 62(-1.4,-1.5)
  silkscreen extent -4.93,-4.15 4.15,4.15, body extent -4,-4 4,4, height 0.98
KNOWLES_SPU0409HD5H-PB [mm] "Silicon MEMS microphone"
  oct 0.8x0.8 smd: 1(0.85,1.23) 4(-0.85,1.23)
  round 0.8 smd: 2(0.85,-1.23) 3(-0.85,-1.23)
  silkscreen extent -1.5,-1.9 1.5,1.9, body extent -1.5,-1.9 1.5,1.9, height 1.1
LDA08C [mm] "PSON, 8-Leads, Body 2.5x3mm, Pitch 0.5mm, NSC Recommended"
  rect 0.5x0.25 smd paste-0.125 mask+0.051: 1(-1.15,0.75) 2(-1.15,0.25) 3(-1.15,-0.25) 4(-1.15,-0.75) 5(1.15,-0.75) 6(1.15,-0.25) 7(1.15,0.25) 8(1.15,0.75)
  rect 1.2x1.5 smd paste-0.6 mask+0.051: 9(0,0)
  silkscreen extent -2.38,-1.45 1.7,1.45, body extent -1.55,-1.3 1.55,1.3, height 0.8
LED_STRIP_PADS_SHORT [mm] "Solder pads for WS2812B-style strips"
  rect 3.5x1.8 smd: 1(0,2.5) 3(0,-2.5)
  rect 3.5x1.6 smd: 2(0,0)
NDK_NX3225SA [mm] "3.2x2.5mm crystal"
  rect 1.4x1.2 smd: 1(0,0) 2(2.2,1.6) 3(2.2,0) 4(0,1.6)
  silkscreen extent -0.72,-1.1 -0.05,-1.1, body extent -0.6,-0.5 2.8,2.1, height 0.7
QFN40P300X300X60-20N [mm] "QFN, 20-Leads, Body 3.0x3.0mm (max), Pitch 0.40mm, IPC Medium Density"
  oval 0.95x0.2 smd mask+0.07: 1(-1.575,0.8) 2(-1.575,0.4) 3(-1.575,0) 4(-1.575,-0.4) 5(-1.575,-0.8) 11(1.575,-0.8) 12(1.575,-0.4) 13(1.575,0) 14(1.575,0.4) 15(1.575,0.8)
  oval 0.2x0.95 smd mask+0.07: 6(-0.8,-1.575) 7(-0.4,-1.575) 8(0,-1.575) 9(0.4,-1.575) 10(0.8,-1.575) 16(0.8,1.575) 17(0.4,1.575) 18(0,1.575) 19(-0.4,1.575) 20(-0.8,1.575)
  silkscreen extent -2.52,0.68 -2.28,0.92, body extent -1.5,-1.5 1.5,1.5, height 0.6
QFN50P400X400-24VBN [mm] "QFN, 24-Leads, Body 4x4mm, Pitch 0.5mm, IPC Medium Density"
  oval 0.8x0.25 smd: 1(-2,1.25) 2(-2,0.75) 3(-2,0.25) 4(-2,-0.25) 5(-2,-0.75) 6(-2,-1.25) 13(2,-1.25) 14(2,-0.75) 15(2,-0.25) 16(2,0.25) 17(2,0.75) 18(2,1.25)
  oval 0.25x0.8 smd: 7(-1.25,-2) 8(-0.75,-2) 9(-0.25,-2) 10(0.25,-2) 11(0.75,-2) 12(1.25,-2) 19(1.25,2) 20(0.75,2) 21(0.25,2) 22(-0.25,2) 23(-0.75,2) 24(-1.25,2)
  rect 2.3x2.3 smd: 25(0,0)
  silkscreen extent -3.07,-2.1 2.1,2.1, body extent -2.07,-2.07 2.07,2.07, height 1
QFN50P500X500-32VAN [mm] "QFN, 32-Leads, Body 5x5mm, Pitch 0.5mm, IPC Medium Density"
  oval 0.8x0.25 smd mask+0.075: 1(-2.5,1.75) 2(-2.5,1.25) 3(-2.5,0.75) 4(-2.5,0.25) 5(-2.5,-0.25) 6(-2.5,-0.75) 7(-2.5,-1.25) 8(-2.5,-1.75) 17(2.5,-1.75) 18(2.5,-1.25) 19(2.5,-0.75) 20(2.5,-0.25) 21(2.5,0.25) 22(2.5,0.75) 23(2.5,1.25) 24(2.5,1.75)
  oval 0.25x0.8 smd mask+0.075: 9(-1.75,-2.5) 10(-1.25,-2.5) 11(-0.75,-2.5) 12(-0.25,-2.5) 13(0.25,-2.5) 14(0.75,-2.5) 15(1.25,-2.5) 16(1.75,-2.5) 25(1.75,2.5) 26(1.25,2.5) 27(0.75,2.5) 28(0.25,2.5) 29(-0.25,2.5) 30(-0.75,2.5) 31(-1.25,2.5) 32(-1.75,2.5)
  rect 3.3x3.3 smd mask+0.075: 33(0,0)
  silkscreen extent -3.58,-2.6 2.6,2.6, body extent -2.58,-2.58 2.58,2.58, height 1
RESC1005N [mm] "Chip Resistor, Body 1.1x0.5mm, IPC Medium Density"
  rect 0.8x0.7 smd: 1(-0.6,0) 2(0.6,0)
  body extent -0.55,-0.3 0.55,0.3, height 0.4
RESC3216N [mm] "Chip Resistor, Body 3.2x1.6mm, IPC Medium Density"
  rect 1.3x1.8 smd: 1(-1.45,0) 2(1.45,0)
  silkscreen extent -0.4,-0.8 0.4,0.8, body extent -1.68,-0.87 1.67,0.87, height 0.71
RESTAP-0603 [mm] "0603 Power tap, cut-trace style"
  rect 0.65x0.8 smd: 1(-0.75,0) 1(0.75,0)
  Top Layer region: -0.504,0.2 0.496,0.2 0.496,-0.2 -0.504,-0.2
  body extent -0.8,-0.4 0.8,0.4, height 0.8
SMA_EDGELAUNCH [mil] "SMA Edge Launch, Generic"
  rect 160x60 smd: 1(0,0)
  rect 160x120 smd far side: 2(0,-130) 2(0,130)
  rect 160x120 smd: 2(0,-130) 2(0,130)
  body extent -75,-188 587,187, height 171
SOD123 [mm] "SOD-123; 2 Leads; Body 2.7 x 1.6 mm, (LxW)"
  rect 1.6x0.8 smd: 1(-1.7,0) 2(1.7,0)
  silkscreen extent -1.45,-0.85 1.45,0.85
SOD-923 [mm] "Molded Diode, 2-Leads, Body 0.80x0.60mm, IPC Medium Density"
  rect 0.3x0.4 smd: 1(-0.45,0) 2(0.45,0)
  silkscreen extent -0.55,0.45 -0.45,0.55, body extent -0.43,-0.33 0.42,0.33, height 0.4
SOT23-5AN [mm] "SOT23, 5-Leads, Body 2.9x1.6mm, Pitch 0.95mm, Lead Span 2.8mm, IPC Medium Density"
  rect 1.1x0.65 smd mask+0.075: 1(-1.2,0.95) 2(-1.2,0) 3(-1.2,-0.95) 4(1.2,-0.95) 5(1.2,0.95)
  silkscreen extent -1.32,-1.55 0.25,1.95, body extent -0.9,-1.55 0.9,1.55, height 1.45
SOT26A-6N [mm] "SOT23, 6-Leads, Body 2.9x1.7mm, Pitch 0.95mm, Lead Span 2.8mm, IPC Medium Density"
  rect 1.1x0.65 smd: 1(-1.2,0.95) 2(-1.2,0) 3(-1.2,-0.95) 4(1.2,-0.95) 5(1.2,0) 6(1.2,0.95)
  silkscreen extent -1.33,-1.55 0.25,1.95, body extent -0.9,-1.55 0.9,1.55, height 1.45
SOT323-3AN [mm] "SOT323, 3-Leads, Body 2.0x1.3mm, Pitch 0.65mm, Lead Span 2.1mm, IPC Medium Density"
  rect 1.2x0.5 smd: 1(-0.95,0.65) 2(-0.95,-0.65) 3(0.95,0)
  silkscreen extent -1.07,-1.1 0.7,1.57, body extent -0.7,-1.1 0.7,1.1, height 1
SOT-23-OT5_N [mm] "SOT23, 5-Leads, Body 2.9x1.6mm, Pitch 0.95mm, Lead Span 2.7mm, IPC Medium Density"
  rect 1.1x0.65 smd: 1(-1.2,0.95) 2(-1.2,0) 3(-1.2,-0.95) 4(1.2,-0.95) 5(1.2,0.95)
  silkscreen extent -1.33,-1.55 0.25,1.95, body extent -0.9,-1.55 0.9,1.55, height 1.45
SWITCH_TS-1187A [mm] "TS-1187A tact switch, Chi Fung Electronics"
  rect 1.5x1.5 smd mask+0.07: 1(0,0) 2(0,-5.5) 3(3.7,0) 4(3.7,-5.5)
  silkscreen extent -0.7,-5.3 4.4,-0.2, body extent -0.7,-5.3 4.4,-0.2, height 1.6
TI_YZF_S_XBGA_N9 [mm] "BGA, 9-Leads, Body 1.58x1.62mmx0.63mm, Pitch 0.50mm"
  round 0.25 smd mask+0.07: A1(-0.5,0.5) A2(0,0.5) A3(0.5,0.5) B1(-0.5,0) B2(0,0) B3(0.5,0) C1(-0.5,-0.5) C2(0,-0.5) C3(0.5,-0.5)
  silkscreen extent -0.94,0.86 -0.85,0.96, body extent -0.79,-0.81 0.79,0.81, height 0.63
TP_HOLE#1 [mm] "Bare wire test point hole"
  rect 2.2x2.2 hole 1.4: 1(0,0)
TP_HOLE#2 [mm] "Bare wire test point hole"
  round 1.143 hole 0.635: 1(0,0)
TP_HOLE#3 [mm] "Bare wire test point hole"
  round 2.2 hole 1.4: 1(0,0)
TP_SMT_38mil [mil] "38 mil round test point, SMT"
  round 38 smd: 1(0,0)
USB_MICRO_B_SMT [mm] "Micro B SMT footprint (based on USB-IF recommended pattern)"
  rect 1.825x0.7 smd mask+0.07: 0(-3,1.7) 0(3,1.7)
  rect 2x1.4 smd mask+0.07: 0(-2.9,3.03) 0(2.9,3.03)
  rrect50% 1.3x3.15 smd mask+0.07: 0(-2.725,0.475) 0(2.725,0.475)
  oval 1.3x1.6 hole 0.66 slot 1.2 at 90 deg mask+0.07: 0(-2.725,0) 0(2.725,0)
  oval 1x1.4 hole 0.66 slot 1.05 at 90 deg mask+0.07: 0(-2.425,3.03) 0(2.425,3.03)
  rect 1.425x2.5 smd mask+0.07: 0(-0.975,-0.25) 0(0.975,-0.25)
  rect 0.4x1.75 smd mask+0.07: 1(-1.3,2.825) 2(-0.65,2.825) 3(0,2.825) 4(0.65,2.825) 5(1.3,2.825)
  silkscreen extent -3.4,-1.7 3.3,-1.7, body extent -4.02,-2.75 4.02,3.28, height 2.85
WS2812B [mm] "3-color RGB LED with internal controller"
  rect 1.5x0.9 smd: 1(-2.45,1.65) 2(-2.45,-1.65) 3(2.45,-1.65) 4(2.45,1.65)
  silkscreen extent -2.5,-2.5 2.5,2.5, body extent -2.5,-2.5 2.5,2.5, height 1.5

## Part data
C10B C10D C10L C10M C10R C10S C10T C11B C11D C11L C11M C11R C11S C11T C12D C12L C12M C12R C12S C13D C13L C13M C13R C13S C14B C14D C14M C14R C14S C15B C15D C15M C15R C15S C16B C16M C16R C16S C17B C17M C17R C17S C18B C18M C18R C18S C19B C19M C19R C19S C20B C20M C20R C21B C21M C21R C22B C22M C23B C23M C24B C24M C25B C25M C26B C26M C27B C27M C28B C28M C29M C30M C31M C32M C33M C34M C35M: library part "Cap Semi", "Capacitor (Semiconductor SIM Model)"
D10B: library part LED2, "White LED 0805"
D10M: library part "D Schottky", "Schottky Diode"
D11B D12B D13B: library part Tranzorb, "TVS Diode, 5V"
J10B J10D J10L J10R J11B J11R J12B J12R J13B J15M J16M J17M: library part CON1, "Connector"
JP10D: "0.96in OLED, 128x64, white"
L10B: library part "Inductor Iron", "Magnetic-Core Inductor"
L10M L10R L11M L11R L12M L12R L13M L13R L14R: library part Inductor, "chip inductor, 0603"
P10L: library part "Header 3", "Header, 3-Pin"
P10M: library part BNC, "50 ohm SMA Edge Launch Connector"
P10R: library part BNC, "U.FL connector"
P11B: library part USB_MINI-AB_1, "Micro USB B type connector"
P11M P15M: library part "Header 6", "Header, 6-Pin"
P12M: library part "Header 12", "Header, 12-Pin"
P16M: "Header, 5-Pin"
Q10B: library part MOSFET-N, "N-Channel MOSFET"
R10D R10M R10R R10S R11D R11M R11R R11S R12D R12M R12R R12S R13D R13M R13S R14D R14M R14S R15D R15M R16B R16D R16M R17B R17D R17M R18B R18D R19B R19D R20B R20D R21B R22B R23B R24B R25B R26B R26T R27B R28B R29B R30B R31B R32B R34T: library part Res1, "Resistor"
SW10M: library part "Header 4", "Chi Fung TS-1187A"
U10B: library part MCP73812T-420I/OT, "Simple, Miniature Single-Cell, Fully Integrated Li-Ion/Li-Polymer Charge Management Controller, 4.2V, 5-Pin SOT-23, Industrial Temperature, Tape and Reel"
U10M: "Freescale Kinetis Integrated Radio + MCU, < 1GHz"
U10R: "BLE single-chip solution"
U10S: library part LP2980M5, "50 mA SOT-23 regulator"
U10T: "Freescale 12-electrode captouch switch sensor IC"
U11M: library part FXL6408, "8-bit I2C GPIO expander"
U11S: "Knowles MEMS silicon microphone"
U12B: library part BQ24260/1/2RGE, "3A, 30V host-controlled single cell Li-ion battery charger"
U12M: "Micropower, Ultra Low-Dropout, Low-Noise, 300mA CMOS Regulator"
U12S: "Rail-to-rail single CMOS op-amp, 5V, 3.7MHz GBW"
U13B: "System-side Impedance Track Gas Gauge"
U13S: "3-axis, 12-bit/8-bit digital accelerometer"
U16L: library part SN74LVC1T45, "Single-gate level translator"
U18L U19L: "RGB LED with integrated controller IC"
Y10M Y10R: library part XTAL, "32 MHz, 7pF CL 10ppm 3225 SMD crystal"

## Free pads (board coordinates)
  round 2.5 hole 2.7 unplated paste-5 mask+2: 0(-20.207,-35.2) 0(-20.207,35.214) 0(20.207,-35.2) 0(20.207,35.214)
  rect 0.203x0.051 on Top Overlay: 1(-13.89,-25.687) 1(-12.925,-24.062) 1(-12.874,-21.674) 1(-12.773,-21.522) 1(-12.468,-22.334) 1(-12.315,-26.703) 1(-11.655,-22.639) 1(-11.503,-24.112) 1(-11.503,-21.826) 1(-11.401,-21.674) 1(-11.35,-21.623) 1(-11.299,-21.522) 1(-11.249,-21.471) 1(-11.198,-21.318) 1(-11.147,-22.284) 1(-11.147,-21.268) 1(-11.096,-22.233) 1(-11.045,-22.182) 1(-10.995,-22.131) 1(-10.741,-21.776) 1(-10.741,-21.725) 1(-10.69,-21.674) 1(-10.639,-21.572) 1(-10.588,-25.586) 1(-10.588,-21.522) 1(-10.588,-21.471) 1(-9.42,-21.877) 1(-9.217,-21.42) 1(-8.658,-21.115) 1(-8.505,-22.944) 1(-8.505,-21.268) 1(-8.455,-21.826) 1(-8.404,-21.776) 1(-8.404,-20.963) 1(-8.353,-21.725) 1(-8.302,-21.674) 1(-8.302,-21.064) 1(-8.251,-21.115) 1(-7.845,-24.112) 1(-7.794,-24.062) 1(-7.794,-22.487) 1(-7.743,-23.96) 1(-7.693,-21.522) 1(-7.642,-22.385) 1(-7.591,-21.674) 1(-7.439,-23.3) 1(-7.439,-22.233) 1(-7.388,-22.182) 1(-7.337,-22.131) 1(-7.286,-22.08) 1(-7.235,-22.03) 1(-7.185,-22.334) 1(-7.185,-21.979) 1(-7.134,-21.928) 1(-7.083,-21.877) 1(-7.032,-21.826) 1(-6.88,-22.588) 1(-6.778,-26.043) 1(-6.727,-24.062) 1(-6.321,-26.043)
  rect 0.254x0.051 on Top Overlay: 1(-13.865,-25.636) 1(-13.814,-25.586) 1(-13.763,-25.535) 1(-13.763,-22.436) 1(-13.712,-25.484) 1(-13.712,-22.385) 1(-13.662,-25.433) 1(-13.611,-25.382) 1(-13.611,-22.334) 1(-13.56,-25.332) 1(-13.509,-22.284) 1(-13.458,-25.179) 1(-13.458,-22.233) 1(-13.408,-25.128) 1(-13.357,-22.182) 1(-13.306,-22.131) 1(-13.255,-22.08) 1(-13.204,-22.03) 1(-13.154,-21.979) 1(-13.001,-21.826) 1(-12.95,-21.776) 1(-12.9,-24.112) 1(-12.9,-21.725) 1(-12.849,-21.623) 1(-12.798,-21.979) 1(-12.798,-21.572) 1(-12.747,-21.471) 1(-12.646,-22.08) 1(-12.595,-22.131) 1(-12.544,-22.182) 1(-12.493,-22.284) 1(-12.493,-22.233) 1(-12.29,-26.652) 1(-12.138,-22.995) 1(-11.579,-22.588) 1(-11.477,-22.538) 1(-11.426,-24.163) 1(-11.426,-22.487) 1(-11.376,-24.214) 1(-11.325,-24.265) 1(-11.325,-22.436) 1(-11.274,-22.385) 1(-11.223,-22.334) 1(-11.172,-21.115) 1(-11.122,-21.217) 1(-11.122,-21.166) 1(-10.664,-21.623) 1(-10.563,-25.535) 1(-10.563,-21.42) 1(-9.801,-24.62) 1(-9.75,-24.57) 1(-9.699,-26.703) 1(-9.699,-21.623) 1(-9.496,-21.776) 1(-9.445,-21.826) 1(-9.445,-21.217) 1(-9.394,-22.538) 1(-9.293,-21.318) 1(-9.242,-21.369) 1(-9.039,-25.332) 1(-8.836,-22.131) 1(-8.785,-22.08) 1(-8.683,-22.03) 1(-8.632,-21.979) 1(-8.582,-21.928) 1(-8.582,-21.166) 1(-8.531,-21.877) 1(-8.531,-21.217) 1(-8.023,-25.128) 1(-7.972,-24.874) 1(-7.972,-24.824) 1(-7.972,-24.773) 1(-7.972,-24.722) 1(-7.972,-24.671) 1(-7.972,-24.62) 1(-7.972,-24.57) 1(-7.769,-24.011) 1(-7.718,-23.909) 1(-7.718,-22.436) 1(-7.667,-23.858) 1(-7.566,-22.334) 1(-7.515,-22.284) 1(-7.159,-25.433) 1(-7.108,-22.385) 1(-6.905,-21.064) 1(-6.804,-21.166) 1(-6.753,-25.992) 1(-6.296,-26.195) 1(-6.296,-26.144) 1(-6.296,-26.094) 1(-2.318,-26.671) 1(-2.318,-21.236) 1(-1.302,-26.367) 1(0.934,-26.367) 1(1.95,-26.671) 1(1.95,-21.236)
  rect 0.102x0.051 on Top Overlay: 1(-13.839,-22.487) 1(-13.636,-21.318) 1(-12.976,-24.011) 1(-12.722,-21.268) 1(-11.757,-22.08) 1(-9.826,-24.671) 1(-9.572,-22.334) 1(-9.572,-22.284) 1(-9.115,-25.382) 1(-8.709,-21.064) 1(-8.455,-21.369) 1(-8.15,-21.471) 1(-7.743,-21.471) 1(-6.88,-22.639) 1(-6.778,-26.094) 1(-2.343,-21.185) 1(-1.276,-26.417) 1(0.908,-26.417) 1(1.975,-21.185)
  rect 0.305x0.051 on Top Overlay: 1(-13.535,-25.281) 1(-13.484,-25.23) 1(-13.382,-25.078) 1(-13.331,-25.027) 1(-13.281,-24.976) 1(-13.281,-24.925) 1(-13.23,-24.874) 1(-13.179,-24.773) 1(-13.128,-24.722) 1(-13.077,-24.62) 1(-12.722,-22.03) 1(-12.671,-21.42) 1(-12.112,-26.195) 1(-12.112,-26.144) 1(-12.112,-26.094) 1(-12.112,-26.043) 1(-12.112,-25.992) 1(-12.112,-25.941) 1(-12.112,-25.89) 1(-12.112,-25.84) 1(-12.112,-25.789) 1(-12.112,-25.738) 1(-12.112,-25.687) 1(-12.112,-25.636) 1(-12.112,-25.586) 1(-12.112,-25.535) 1(-12.112,-25.484) 1(-12.112,-25.433) 1(-12.112,-25.382) 1(-12.112,-25.332) 1(-12.112,-25.281) 1(-12.112,-25.23) 1(-12.112,-25.179) 1(-12.112,-25.128) 1(-12.112,-25.078) 1(-12.112,-25.027) 1(-12.112,-24.976) 1(-12.112,-24.925) 1(-12.112,-24.874) 1(-12.112,-24.824) 1(-12.112,-24.773) 1(-12.112,-24.722) 1(-12.112,-24.671) 1(-12.112,-24.62) 1(-12.112,-24.57) 1(-12.112,-24.519) 1(-12.112,-24.468) 1(-12.112,-24.417) 1(-12.112,-24.366) 1(-12.112,-24.316) 1(-12.112,-24.265) 1(-12.112,-24.214) 1(-12.112,-24.163) 1(-12.112,-24.112) 1(-12.112,-24.062) 1(-12.112,-24.011) 1(-12.112,-23.96) 1(-12.112,-23.909) 1(-12.112,-23.858) 1(-12.112,-23.808) 1(-12.112,-23.757) 1(-12.112,-23.706) 1(-12.112,-23.655) 1(-12.112,-23.604) 1(-12.112,-23.554) 1(-12.112,-23.503) 1(-12.112,-23.452) 1(-12.112,-23.401) 1(-12.112,-23.35) 1(-12.112,-23.3) 1(-12.112,-23.249) 1(-11.299,-24.316) 1(-11.249,-24.366) 1(-11.198,-24.417) 1(-10.842,-21.979) 1(-10.842,-21.928) 1(-10.588,-25.484) 1(-9.674,-24.519) 1(-9.623,-24.468) 1(-9.521,-21.725) 1(-9.42,-24.316) 1(-9.115,-24.011) 1(-9.115,-22.334) 1(-9.064,-22.284) 1(-9.013,-25.281) 1(-9.013,-25.23) 1(-9.013,-25.179) 1(-9.013,-25.128) 1(-9.013,-24.976) 1(-9.013,-24.925) 1(-9.013,-24.874) 1(-9.013,-24.824) 1(-9.013,-24.773) 1(-9.013,-24.722) 1(-9.013,-24.671) 1(-9.013,-24.62) 1(-9.013,-24.57) 1(-9.013,-24.519) 1(-9.013,-24.468) 1(-9.013,-24.417) 1(-9.013,-24.366) 1(-9.013,-24.316) 1(-8.963,-22.233) 1(-8.912,-22.182) 1(-8.353,-21.014) 1(-8.251,-25.789) 1(-8.201,-25.687) 1(-8.15,-25.586) 1(-8.15,-25.535) 1(-8.099,-25.484) 1(-8.099,-25.433) 1(-8.099,-25.382) 1(-8.048,-25.332) 1(-8.048,-25.281) 1(-8.048,-25.23) 1(-8.048,-25.179) 1(-7.997,-24.976) 1(-7.997,-24.925) 1(-7.947,-24.519) 1(-7.947,-24.468) 1(-7.947,-24.417) 1(-7.947,-24.366) 1(-7.947,-24.316) 1(-7.642,-26.195) 1(-7.642,-26.144) 1(-7.642,-26.094) 1(-7.642,-26.043) 1(-7.642,-25.992) 1(-7.642,-25.941) 1(-7.642,-25.89) 1(-7.642,-25.84) 1(-7.642,-25.789) 1(-7.642,-25.738) 1(-7.642,-25.687) 1(-7.642,-25.636) 1(-7.642,-25.586) 1(-7.642,-25.535) 1(-7.642,-25.484) 1(-7.642,-25.433) 1(-7.642,-25.382) 1(-7.642,-25.332) 1(-7.642,-25.281) 1(-7.642,-25.23) 1(-7.642,-25.179) 1(-7.642,-25.128) 1(-7.642,-23.808) 1(-7.591,-23.757) 1(-7.439,-23.35) 1(-6.88,-22.538) 1(-6.88,-21.674) 1(-6.88,-21.623) 1(-6.778,-25.941) 1(-6.778,-25.89) 1(-6.727,-25.23) 1(-6.727,-25.179) 1(-6.727,-25.128) 1(-6.727,-24.976) 1(-6.727,-24.925) 1(-6.727,-24.874) 1(-6.727,-24.824) 1(-6.727,-24.773) 1(-6.727,-24.722) 1(-6.727,-24.671) 1(-6.727,-24.62) 1(-6.727,-24.57) 1(-6.727,-24.519) 1(-6.727,-24.468) 1(-6.727,-24.417) 1(-6.727,-24.366) 1(-6.727,-24.316) 1(-6.727,-24.112) 1(-6.27,-21.471)
  rect 0.152x0.051 on Top Overlay: 1(-13.458,-21.522) 1(-12.442,-22.385) 1(-12.188,-22.944) 1(-11.731,-22.03) 1(-11.68,-21.979) 1(-11.63,-21.928) 1(-11.579,-21.877) 1(-11.528,-24.062) 1(-11.477,-21.776) 1(-11.325,-21.572) 1(-11.223,-21.064) 1(-10.563,-25.636) 1(-10.563,-21.268) 1(-9.394,-22.588) 1(-9.191,-21.471) 1(-8.531,-22.893) 1(-8.48,-21.318) 1(-8.277,-21.623) 1(-8.226,-21.572) 1(-8.226,-21.166) 1(-8.175,-21.522) 1(-7.21,-25.382) 1(-6.804,-25.281) 1(-6.804,-22.385) 1(-6.804,-22.334) 1(-6.804,-22.284) 1(-6.804,-22.233) 1(-6.804,-22.182) 1(-6.804,-22.131) 1(-6.804,-22.08) 1(-6.804,-22.03) 1(-6.804,-21.979) 1(-6.804,-21.928) 1(-6.804,-21.877) 1(-6.804,-21.826) 1(-6.804,-21.471) 1(-6.804,-21.42) 1(-6.804,-21.369) 1(-6.804,-21.318) 1(-6.804,-21.268) 1(-6.804,-21.217) 1(-6.753,-24.011) 1(-6.296,-25.992) 1(-6.296,-25.941) 1(-6.296,-25.89) 1(-6.296,-25.84) 1(-6.296,-25.789) 1(-6.296,-25.738) 1(-6.296,-25.687) 1(-6.296,-25.636) 1(-6.296,-25.586) 1(-2.318,-26.722) 1(1.95,-26.722)
  rect 0.406x0.051 on Top Overlay: 1(-13.433,-21.471) 1(-13.027,-24.519) 1(-12.976,-24.417) 1(-12.925,-24.366) 1(-12.773,-21.318) 1(-12.722,-26.246) 1(-12.265,-26.551) 1(-12.061,-23.147) 1(-11.147,-21.42) 1(-11.045,-24.57) 1(-10.995,-24.62) 1(-10.944,-24.671) 1(-10.893,-24.722) 1(-10.893,-22.08) 1(-10.893,-21.877) 1(-10.842,-24.824) 1(-10.842,-22.03) 1(-10.588,-25.382) 1(-10.588,-25.332) 1(-10.588,-25.281) 1(-9.369,-22.487) 1(-8.759,-26.297) 1(-8.658,-26.246) 1(-8.658,-23.35) 1(-8.607,-26.195) 1(-8.607,-23.3) 1(-8.556,-26.144) 1(-8.556,-23.249) 1(-8.455,-23.046) 1(-7.591,-26.297) 1(-7.54,-26.348) 1(-7.439,-23.401) 1(-6.981,-25.586) 1(-6.931,-25.636) 1(-6.931,-22.436) 1(-6.931,-21.776) 1(-6.88,-25.687) 1(-6.829,-25.789) 1(-6.829,-25.738) 1(-6.27,-26.297) 1(-2.292,-26.621)
  rect 0.762x0.051 on Top Overlay: 1(-13.255,-21.42) 1(-12.341,-26.398) 1(-2.267,-26.468) 1(-2.267,-21.439) 1(1.899,-26.468)
  rect 0.356x0.051 on Top Overlay: 1(-13.204,-24.824) 1(-13.103,-24.671) 1(-13.052,-24.57) 1(-13.001,-24.468) 1(-13.001,-21.877) 1(-12.9,-24.163) 1(-12.29,-26.602) 1(-12.138,-26.246) 1(-12.087,-23.198) 1(-12.087,-23.046) 1(-11.122,-24.468) 1(-11.122,-21.776) 1(-11.071,-24.519) 1(-10.563,-25.433) 1(-9.648,-21.674) 1(-9.547,-24.417) 1(-9.496,-24.366) 1(-9.394,-21.268) 1(-9.14,-24.062) 1(-9.09,-23.96) 1(-9.039,-23.909) 1(-8.988,-23.858) 1(-8.937,-23.808) 1(-8.937,-23.757) 1(-8.886,-23.706) 1(-8.836,-23.655) 1(-8.836,-23.604) 1(-8.785,-23.554) 1(-8.683,-23.401) 1(-8.48,-26.094) 1(-8.48,-22.995) 1(-8.429,-26.043) 1(-8.378,-25.992) 1(-8.378,-25.941) 1(-8.328,-25.89) 1(-8.277,-25.84) 1(-8.226,-25.738) 1(-8.175,-25.636) 1(-7.616,-26.246) 1(-7.566,-23.706) 1(-7.515,-23.655) 1(-7.108,-25.484) 1(-7.058,-25.535) 1(-6.905,-22.487) 1(-6.905,-21.725) 1(-6.854,-21.115) 1(-6.804,-25.84) 1(-6.296,-26.246) 1(-2.318,-21.287) 1(-1.352,-26.316) 1(0.984,-26.316) 1(1.95,-26.621) 1(1.95,-21.287)
  rect 1.118x0.051 on Top Overlay: 1(-13.128,-21.369) 1(-2.241,-26.316) 1(-2.241,-21.591) 1(-0.159,-20.931) 1(1.873,-26.316) 1(1.873,-21.591)
  rect 0.508x0.051 on Top Overlay: 1(-12.976,-21.928) 1(-12.874,-24.316) 1(-12.874,-24.265) 1(-11.299,-21.725) 1(-10.944,-21.826) 1(-9.471,-26.602) 1(-9.369,-22.436) 1(-9.318,-26.551) 1(-9.166,-26.5) 1(-8.455,-23.096) 1(-7.388,-23.554) 1(-6.27,-26.348) 1(-2.292,-26.57) 1(-2.292,-21.337) 1(1.924,-26.57)
  rect 0.457x0.051 on Top Overlay: 1(-12.849,-24.214) 1(-12.036,-23.096) 1(-10.868,-24.773) 1(-10.817,-24.874) 1(-10.766,-24.925) 1(-10.715,-25.027) 1(-10.715,-24.976) 1(-10.664,-25.128) 1(-10.664,-25.078) 1(-10.614,-25.23) 1(-10.614,-25.179) 1(-9.598,-26.652) 1(-9.14,-24.112) 1(-9.039,-26.449) 1(-8.937,-26.398) 1(-8.836,-26.348) 1(-8.531,-23.198) 1(-8.48,-23.147) 1(-7.464,-23.604) 1(1.95,-21.337)
  rect 0.965x0.051 on Top Overlay: 1(-12.442,-26.297) 1(-2.267,-21.541) 1(-0.184,-20.575) 1(-0.184,-20.525) 1(-0.184,-20.474) 1(1.899,-21.541)
  rect 0.914x0.051 on Top Overlay: 1(-12.417,-26.348) 1(-10.842,-21.369)
  rect 0.61x0.051 on Top Overlay: 1(-12.315,-26.449) 1(-10.69,-21.318) 1(-9.318,-22.385) 1(-7.439,-21.623) 1(-2.292,-21.388) 1(1.924,-26.519) 1(1.924,-21.388)
  rect 0.559x0.051 on Top Overlay: 1(-12.29,-26.5)
  rect 0.051x0.051 on Top Overlay: 1(-11.68,-22.69) 1(-11.528,-24.011) 1(-8.226,-21.217) 1(-7.82,-22.538) 1(-7.464,-23.249) 1(-7.21,-22.284)
  rect 1.727x0.051 on Top Overlay: 1(-8.048,-23.452) 1(-6.88,-26.398) 1(-1.987,-26.265) 1(-1.733,-25.554) 1(-1.683,-25.452) 1(-1.632,-25.401) 1(-1.632,-25.351) 1(-1.632,-25.3) 1(-0.159,-21.49) 1(1.264,-25.351) 1(1.264,-25.3) 1(1.315,-25.452) 1(1.365,-25.554)
  rect 2.997x0.051 on Top Overlay: 1(-8.023,-24.265) 1(-7.972,-24.214)
  rect 1.778x0.051 on Top Overlay: 1(-8.023,-23.503) 1(-6.905,-21.572) 1(-2.013,-26.214) 1(-1.81,-25.706) 1(-1.81,-25.655) 1(-1.759,-25.605) 1(-1.708,-25.503) 1(1.34,-25.503) 1(1.391,-25.605) 1(1.442,-25.706) 1(1.442,-25.655) 1(1.492,-25.757) 1(1.645,-26.214)
  rect 2.946x0.051 on Top Overlay: 1(-7.947,-24.163)
  rect 2.591x0.051 on Top Overlay: 1(-7.87,-25.078) 1(-7.87,-25.027) 1(-2.419,-24.385) 1(-2.419,-24.335) 1(-2.419,-24.284) 1(-2.419,-23.623) 1(-2.419,-23.573) 1(-2.368,-24.436) 1(2,-24.436) 1(2.051,-24.385) 1(2.051,-24.335) 1(2.051,-23.623) 1(2.051,-23.573) 1(2.051,-23.522)
  rect 1.372x0.051 on Top Overlay: 1(-6.905,-26.602)
  rect 1.473x0.051 on Top Overlay: 1(-6.905,-26.551) 1(-0.184,-21.439)
  rect 1.676x0.051 on Top Overlay: 1(-6.905,-26.449) 1(1.289,-25.401) 1(1.645,-26.265)
  rect 1.626x0.051 on Top Overlay: 1(-6.88,-26.5)
  rect 1.27x0.051 on Top Overlay: 1(-6.702,-21.522) 1(-0.184,-21.388) 1(-0.184,-21.337) 1(-0.184,-21.287) 1(-0.184,-21.236)
  rect 2.54x0.051 on Top Overlay: 1(-2.445,-24.233) 1(-2.445,-24.182) 1(-2.445,-24.131) 1(-2.445,-24.081) 1(-2.445,-24.03) 1(-2.445,-23.979) 1(-2.445,-23.928) 1(-2.445,-23.877) 1(-2.445,-23.827) 1(-2.445,-23.776) 1(-2.445,-23.725) 1(-2.445,-23.674) 1(-2.343,-23.471) 1(1.975,-23.471) 1(2.077,-24.284) 1(2.077,-24.233) 1(2.077,-24.182) 1(2.077,-24.131) 1(2.077,-24.081) 1(2.077,-23.877) 1(2.077,-23.827) 1(2.077,-23.776) 1(2.077,-23.725) 1(2.077,-23.674)
  rect 2.642x0.051 on Top Overlay: 1(-2.394,-23.522)
  rect 0.66x0.051 on Top Overlay: 1(-2.267,-26.519)
  rect 0.864x0.051 on Top Overlay: 1(-2.267,-26.417) 1(-2.267,-21.49) 1(-0.184,-20.423) 1(1.899,-26.417) 1(1.899,-21.49)
  rect 1.016x0.051 on Top Overlay: 1(-2.241,-26.367) 1(-0.159,-20.626) 1(1.873,-26.367)
  rect 2.337x0.051 on Top Overlay: 1(-2.241,-24.487) 1(1.111,-22.963) 1(1.873,-24.487)
  rect 1.219x0.051 on Top Overlay: 1(-2.241,-21.642) 1(-0.159,-21.185) 1(1.873,-21.642)
  rect 2.286x0.051 on Top Overlay: 1(-2.165,-23.42) 1(-1.454,-22.963) 1(1.848,-23.42)
  rect 2.134x0.051 on Top Overlay: 1(-2.089,-24.538) 1(-1.581,-23.014) 1(1.213,-23.014) 1(1.721,-24.538)
  rect 1.829x0.051 on Top Overlay: 1(-2.038,-26.163) 1(-1.937,-25.909) 1(-1.886,-25.859) 1(-1.886,-25.808) 1(-1.886,-23.319) 1(-1.835,-25.757) 1(-1.835,-24.69) 1(-1.835,-24.639) 1(-1.835,-23.268) 1(-1.784,-23.217) 1(-1.632,-25.249) 1(-1.632,-25.198) 1(1.264,-25.249) 1(1.264,-25.198) 1(1.467,-24.69) 1(1.467,-23.268) 1(1.518,-25.808) 1(1.518,-24.639) 1(1.518,-23.319) 1(1.569,-25.909) 1(1.67,-26.163)
  rect 1.93x0.051 on Top Overlay: 1(-2.038,-26.113) 1(-1.784,-24.741) 1(-1.733,-24.792) 1(-1.733,-23.115) 1(-1.632,-25.097) 1(-1.632,-25.046) 1(1.264,-25.097) 1(1.264,-25.046) 1(1.365,-24.792) 1(1.365,-23.115) 1(1.67,-26.113)
  rect 2.032x0.051 on Top Overlay: 1(-2.038,-23.369) 1(-1.632,-24.995) 1(-1.632,-24.944) 1(-1.632,-24.893) 1(1.264,-24.995) 1(1.264,-24.944) 1(1.315,-24.893) 1(1.67,-23.369)
  rect 1.88x0.051 on Top Overlay: 1(-2.013,-26.062) 1(-1.962,-26.011) 1(-1.962,-25.96) 1(-1.911,-24.589) 1(-1.759,-23.166) 1(-1.606,-25.147) 1(1.289,-25.147) 1(1.391,-23.166) 1(1.442,-24.741) 1(1.442,-23.217) 1(1.543,-25.859) 1(1.543,-24.589) 1(1.594,-25.96) 1(1.645,-26.062) 1(1.645,-26.011)
  rect 1.981x0.051 on Top Overlay: 1(-1.708,-24.843) 1(-1.657,-23.065) 1(-0.184,-21.541) 1(1.289,-23.065) 1(1.34,-24.843)
  rect 4.826x0.051 on Top Overlay: 1(-0.184,-22.912) 1(-0.184,-22.861) 1(-0.184,-22.404)
  rect 4.724x0.051 on Top Overlay: 1(-0.184,-22.811) 1(-0.184,-22.76) 1(-0.184,-22.455)
  rect 4.623x0.051 on Top Overlay: 1(-0.184,-22.709) 1(-0.184,-22.658) 1(-0.184,-22.607) 1(-0.184,-22.557)
  rect 4.928x0.051 on Top Overlay: 1(-0.184,-22.303)
  rect 5.029x0.051 on Top Overlay: 1(-0.184,-22.252)
  rect 5.131x0.051 on Top Overlay: 1(-0.184,-22.15)
  rect 5.232x0.051 on Top Overlay: 1(-0.184,-22.099)
  rect 5.334x0.051 on Top Overlay: 1(-0.184,-22.049) 1(-0.184,-21.998)
  rect 5.436x0.051 on Top Overlay: 1(-0.184,-21.947) 1(-0.184,-21.693)
  rect 5.537x0.051 on Top Overlay: 1(-0.184,-21.896) 1(-0.184,-21.845) 1(-0.184,-21.744)
  rect 5.639x0.051 on Top Overlay: 1(-0.184,-21.795)
  rect 2.489x0.051 on Top Overlay: 1(-0.184,-21.642) 1(2.102,-24.03) 1(2.102,-23.979) 1(2.102,-23.928)
  rect 2.184x0.051 on Top Overlay: 1(-0.184,-21.591)
  rect 1.168x0.051 on Top Overlay: 1(-0.184,-21.134) 1(-0.184,-21.083) 1(-0.184,-21.033) 1(-0.184,-20.982)
  rect 1.067x0.051 on Top Overlay: 1(-0.184,-20.88) 1(-0.184,-20.829) 1(-0.184,-20.779) 1(-0.184,-20.728) 1(-0.184,-20.677)
  rect 4.674x0.051 on Top Overlay: 1(-0.159,-22.506)
  rect 4.877x0.051 on Top Overlay: 1(-0.159,-22.353)
  rect 5.08x0.051 on Top Overlay: 1(-0.159,-22.201)
  rect 0.711x0.051 on Top Overlay: 1(1.924,-21.439)

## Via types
v1: diameter 0.5, hole 0.25, Top Layer to Bottom Layer, tented both sides, 320 vias
v2: diameter 0.5, hole 0.2, Top Layer to Bottom Layer, 18 vias
v3: diameter 0.66, hole 0.33, Top Layer to Bottom Layer, tented top, 13 vias
v4: diameter 0.5, hole 0.2, Top Layer to Bottom Layer, tented top, 2 vias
